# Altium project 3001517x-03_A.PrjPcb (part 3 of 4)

## Sheet 10 - CAN, I2C, XBee.SchDoc: CAN, I2C, XBee
size A3; PageSetup: Record=PageOptions¦CenterHorizontal=True¦CenterVertical=True¦PrintScale=0.70¦XCorrection=1.00¦YCorrection=1.00¦PrintKind=0¦BorderSize=5000000¦LeftOffset=0¦BottomOffset=0¦Orientation=2¦PaperLength=4200¦PaperWidth=2970¦Scale=100¦PaperSource=7¦PrintQuality=600¦MediaType=1¦DitherType=10¦PaperKind=A4¦PrintScaleMode=1; Author: Sébastien MEYER; SheetNumber: 10; SheetTotal: 14
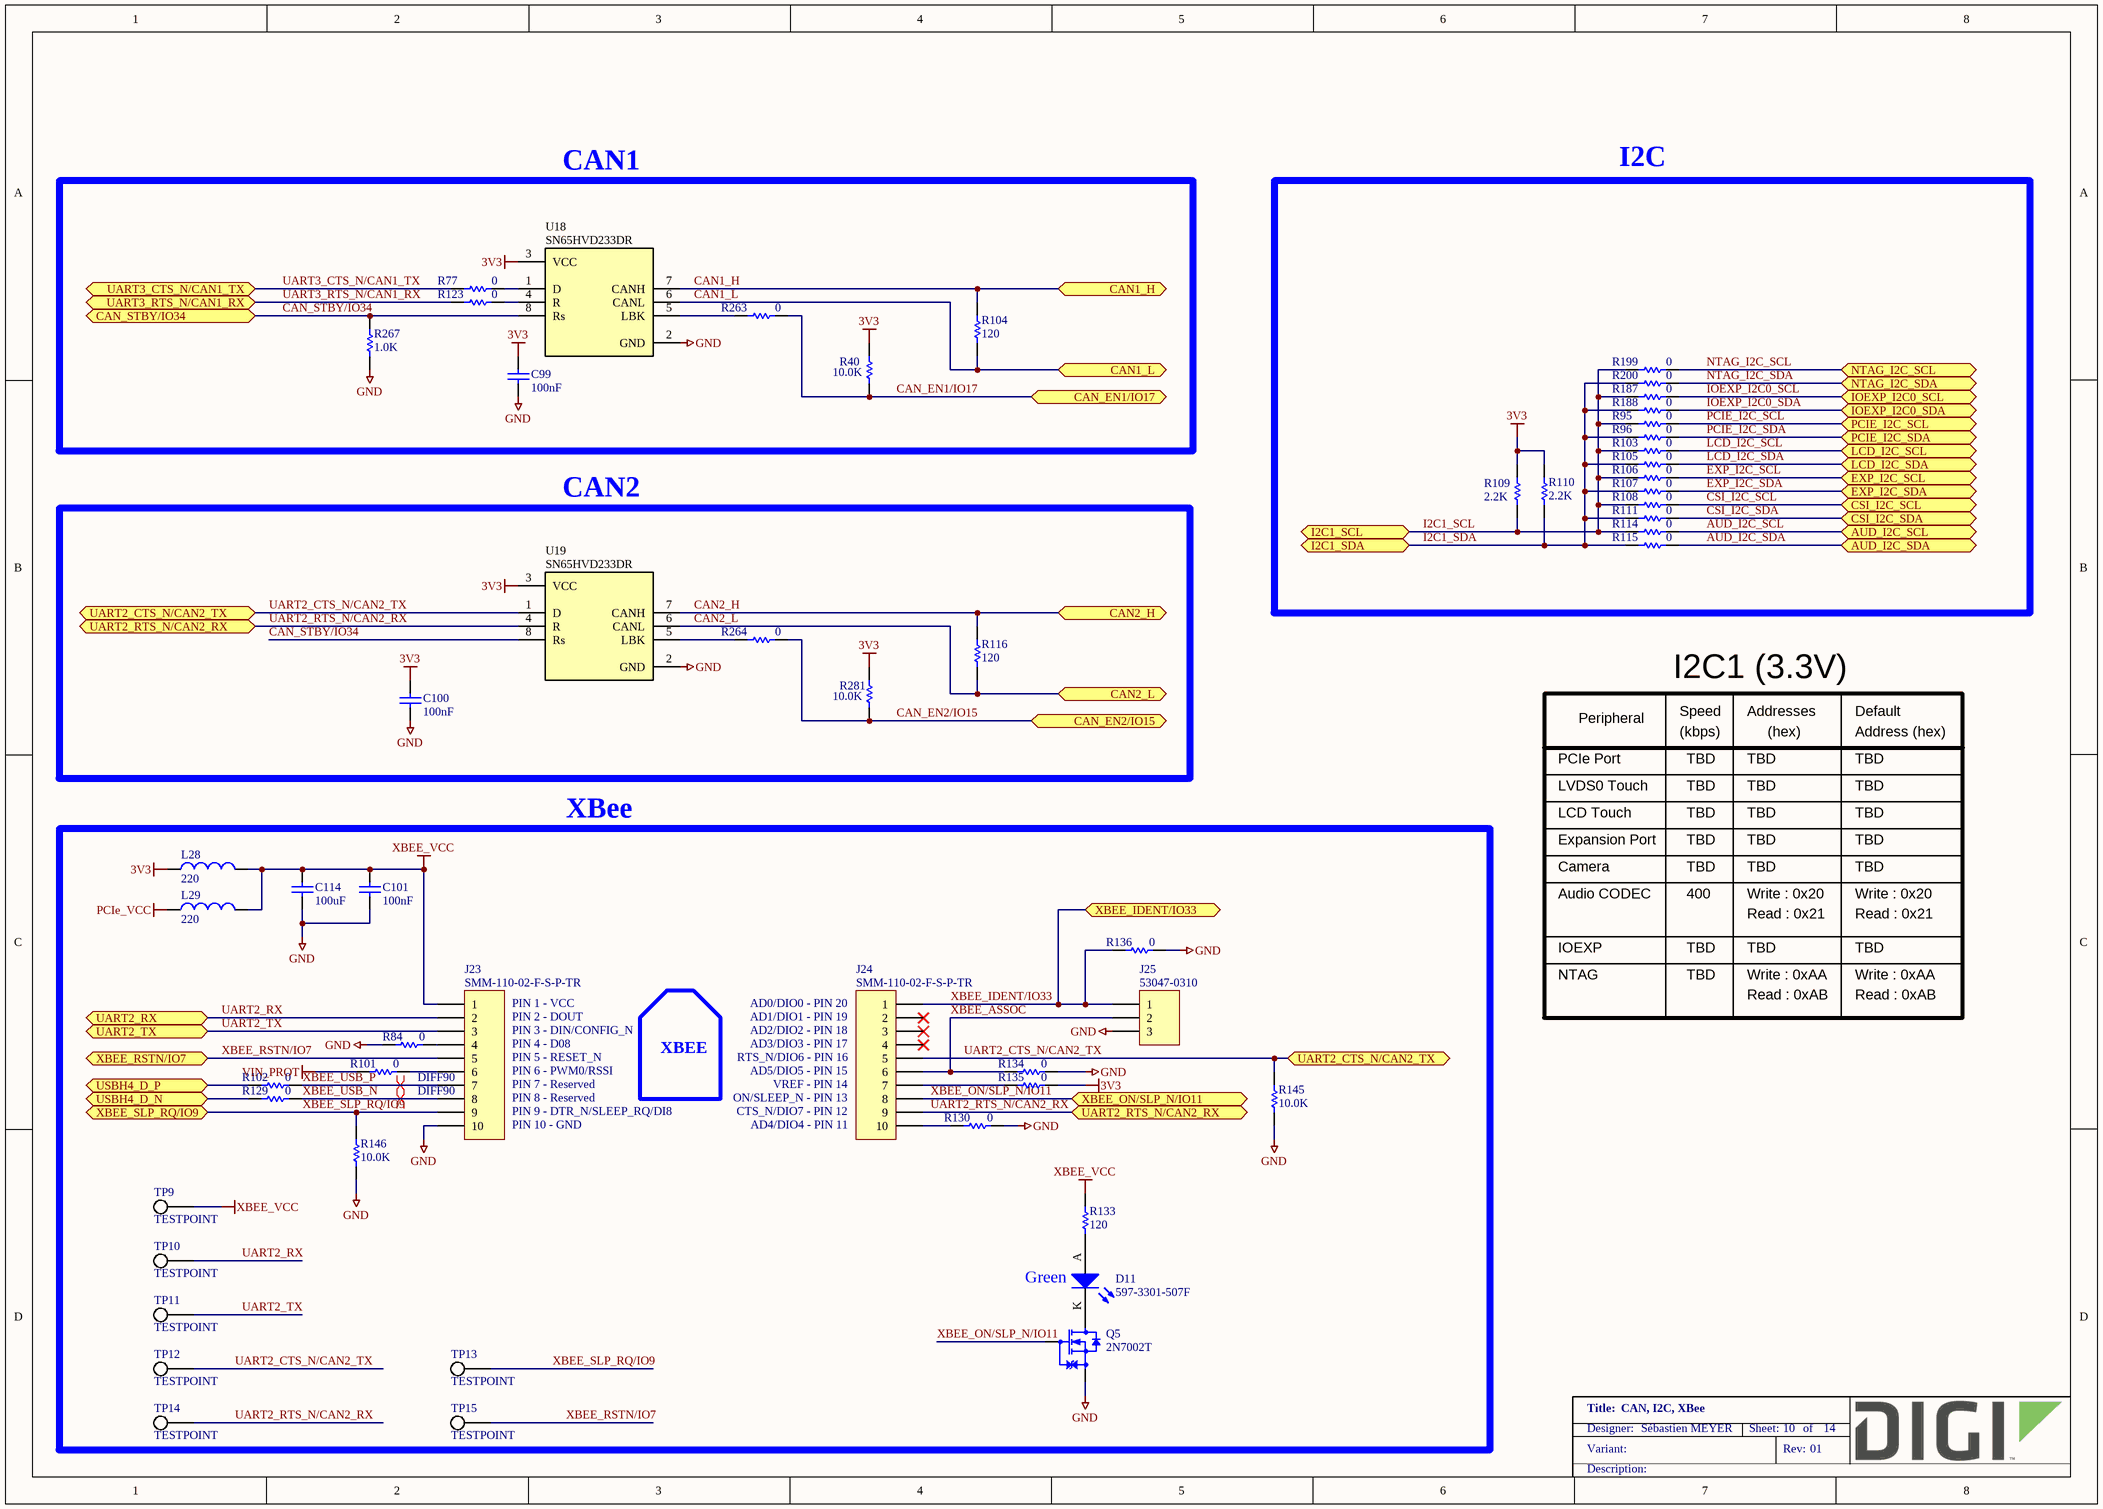
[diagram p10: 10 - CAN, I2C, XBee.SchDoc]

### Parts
C99  100nF  [CAPC1005X55N]
C100  100nF  [CAPC1005X55N]
C101  100nF  [CAPC1005X55N]
C114  100uF  [CAPC3216X190N]
D11  597-3301-507F  [LEDM3020X130N]
J23  SMM-110-02-F-S-P-TR  [Samtec_SMM-110-02-F-S]
J24  SMM-110-02-F-S-P-TR  [Samtec_SMM-110-02-F-S]
J25  Manufacturer_Part_Number: 53047-0310  [MOLEX_53047-0310]  (hidden comment: 1x3P)
L28  220  [INDC2013X110N]
L29  220  [INDC2013X110N]
Q5  2N7002T  [SOTFL50P160X80_GSD-3N]
R40  10.0K  [RESC1005X40N]
R77  0  [RESC1005X40N]
R84  0  [RESC1005X40N]
R95  0  [RESC1005X40N]
R96  0  [RESC1005X40N]
R101  0  [RESC1005X40N]
R102  0  [RESC1005X40N]
R103  0  [RESC1005X40N]
R104  120  [RESC1005X40N]
R105  0  [RESC1005X40N]
R106  0  [RESC1005X40N]
R107  0  [RESC1005X40N]
R108  0  [RESC1005X40N]
R109  2.2K  [RESC1005X40N]
R110  2.2K  [RESC1005X40N]
R111  0  [RESC1005X40N]
R114  0  [RESC1005X40N]
R115  0  [RESC1005X40N]
R116  120  [RESC1005X40N]
R123  0  [RESC1005X40N]
R129  0  [RESC1005X40N]
R130  0  [RESC1005X40N]
R133  120  [RESC1005X40N]
R134  0  [RESC1005X40N]
R135  0  [RESC1005X40N]
R136  0  [RESC1005X40N]
R145  10.0K  [RESC1005X40N]
R146  10.0K  [RESC1005X40N]
R187  0  [RESC1005X40N]
R188  0  [RESC1005X40N]
R199  0  [RESC1005X40N]
R200  0  [RESC1005X40N]
R263  0  [RESC1005X40N]
R264  0  [RESC1005X40N]
R267  1.0K  [RESC1005X40N]
R281  10.0K  [RESC1005X40N]
TP9  TESTPOINT  [TP0762]  (no BOM)
TP10  TESTPOINT  [TP0762]  (no BOM)
TP11  TESTPOINT  [TP0762]  (no BOM)
TP12  TESTPOINT  [TP0762]  (no BOM)
TP13  TESTPOINT  [TP0762]  (no BOM)
TP14  TESTPOINT  [TP0762]  (no BOM)
TP15  TESTPOINT  [TP0762]  (no BOM)
U18  SN65HVD233DR  [SOIC127P600X175-8N]
U19  SN65HVD233DR  [SOIC127P600X175-8N]

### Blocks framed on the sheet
CAN1: C99 R40 R77 R104 R123 R263 R267 U18
I2C: R95 R96 R103 R105-R111 R114 R115 R187 R188 R199 R200
CAN2: C100 R116 R264 R281 U19
XBee: C101 C114 D11 J23-J25 L28 L29 Q5 R84 R101 R102 R129 R130 R133-R136 R145 R146 TP9-TP15

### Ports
AUD_I2C_SCL (bidir), AUD_I2C_SDA (bidir), CAN1_H (bidir), CAN1_L (bidir), CAN2_H (bidir), CAN2_L (bidir), CAN_EN1/IO17 (bidir), CAN_EN2/IO15 (bidir), CAN_STBY/IO34 (bidir), CSI_I2C_SCL (bidir), CSI_I2C_SDA (bidir), EXP_I2C_SCL (bidir), EXP_I2C_SDA (bidir), I2C1_SCL (bidir), I2C1_SDA (bidir), IOEXP_I2C0_SCL (bidir), IOEXP_I2C0_SDA (bidir), LCD_I2C_SCL (bidir), LCD_I2C_SDA (bidir), NTAG_I2C_SCL (bidir), NTAG_I2C_SDA (bidir), PCIE_I2C_SCL (bidir), PCIE_I2C_SDA (bidir), UART2_CTS_N/CAN2_TX (bidir), UART2_RTS_N/CAN2_RX (bidir), UART2_RX (bidir), UART2_TX (bidir), UART3_CTS_N/CAN1_TX (bidir), UART3_RTS_N/CAN1_RX (bidir), USBH4_D_N (bidir), USBH4_D_P (bidir), XBEE_IDENT/IO33 (bidir), XBEE_ON/SLP_N/IO11 (bidir), XBEE_RSTN/IO7 (bidir), XBEE_SLP_RQ/IO9 (bidir)

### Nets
3V3: C99.2 C100.2 L28.1 R40.1 R109.2 R110.2 R135.2 R281.1 U18.3(VCC) U19.3(VCC)
GND: C99.1 C100.1 C101.1 C114.1 J23.10 J25.3 Q5.S R84.1 R130.2 R134.2 R136.2 R145.1 R146.1 R267.2 U18.2(GND) U19.2(GND)
PCIe_VCC: L29.1
VIN_PROT: R101.1
XBEE_VCC: C101.2 C114.2 J23.1 L28.2 L29.2 R133.1 TP9.1
AUD_I2C_SCL: R114.2 ; port AUD_I2C_SCL
AUD_I2C_SDA: R115.2 ; port AUD_I2C_SDA
CAN1_H: R104.2 U18.7(CANH) ; port CAN1_H
CAN1_L: R104.1 U18.6(CANL) ; port CAN1_L
CAN2_H: R116.2 U19.7(CANH) ; port CAN2_H
CAN2_L: R116.1 U19.6(CANL) ; port CAN2_L
CAN_EN1/IO17: R40.2 R263.2 ; port CAN_EN1/IO17
CAN_EN2/IO15: R264.2 R281.2 ; port CAN_EN2/IO15
CAN_STBY/IO34: R267.1 U18.8(Rs) U19.8(Rs) ; port CAN_STBY/IO34
CSI_I2C_SCL: R108.2 ; port CSI_I2C_SCL
CSI_I2C_SDA: R111.2 ; port CSI_I2C_SDA
EXP_I2C_SCL: R106.2 ; port EXP_I2C_SCL
EXP_I2C_SDA: R107.2 ; port EXP_I2C_SDA
I2C1_SCL: R95.1 R103.1 R106.1 R108.1 R109.1 R114.1 R187.1 R199.1 ; port I2C1_SCL
I2C1_SDA: R96.1 R105.1 R107.1 R110.1 R111.1 R115.1 R188.1 R200.1 ; port I2C1_SDA
IOEXP_I2C0_SCL: R187.2 ; port IOEXP_I2C0_SCL
IOEXP_I2C0_SDA: R188.2 ; port IOEXP_I2C0_SDA
LCD_I2C_SCL: R103.2 ; port LCD_I2C_SCL
LCD_I2C_SDA: R105.2 ; port LCD_I2C_SDA
NTAG_I2C_SCL: R199.2 ; port NTAG_I2C_SCL
NTAG_I2C_SDA: R200.2 ; port NTAG_I2C_SDA
PCIE_I2C_SCL: R95.2 ; port PCIE_I2C_SCL
PCIE_I2C_SDA: R96.2 ; port PCIE_I2C_SDA
UART2_CTS_N/CAN2_TX: J24.5 R145.2 TP12.1 U19.1(D) ; port UART2_CTS_N/CAN2_TX
UART2_RTS_N/CAN2_RX: J24.9 TP14.1 U19.4(R) ; port UART2_RTS_N/CAN2_RX
UART2_RX: J23.2 TP10.1 ; port UART2_RX
UART2_TX: J23.3 TP11.1 ; port UART2_TX
UART3_CTS_N/CAN1_TX: R77.1 ; port UART3_CTS_N/CAN1_TX
UART3_RTS_N/CAN1_RX: R123.1 ; port UART3_RTS_N/CAN1_RX
USBH4_D_N: R129.1 ; port USBH4_D_N
USBH4_D_P: R102.1 ; port USBH4_D_P
XBEE_ASSOC: J24.6 J25.2 R134.1
XBEE_IDENT/IO33: J24.1 J25.1 R136.1 ; port XBEE_IDENT/IO33
XBEE_ON/SLP_N/IO11: J24.8 Q5.G ; port XBEE_ON/SLP_N/IO11
XBEE_RSTN/IO7: J23.5 TP15.1 ; port XBEE_RSTN/IO7
XBEE_SLP_RQ/IO9: J23.9 R146.2 TP13.1 ; port XBEE_SLP_RQ/IO9
XBEE_USB_N: J23.8 R129.2
XBEE_USB_P: J23.7 R102.2
NetD11_A: D11.A R133.2
NetD11_K: D11.K Q5.D
NetJ23_4: J23.4 R84.2
NetJ23_6: J23.6 R101.2
NetJ24_7: J24.7 R135.1
NetJ24_10: J24.10 R130.1
NetR77_2: R77.2 U18.1(D)
NetR123_2: R123.2 U18.4(R)
NetR263_1: R263.1 U18.5(LBK)
NetR264_1: R264.1 U19.5(LBK)

Not connected (* = marked no-connect by the designer): J24 2* 3* 4*

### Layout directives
differential pair; net class DIFF90: XBEE_USB_N, XBEE_USB_P

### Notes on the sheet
- Peripheral
- I2C1 (3.3V)
- Speed
- Addresses
- Default
- PCIe Port
- (kbps)
- TBD
- (hex)
- Address (hex)
- LVDS0 Touch
- LCD Touch
- Expansion Port
- Camera
- Audio CODEC
- 400
- Write : 0x20
- Read : 0x21
- IOEXP
- NTAG
- Write : 0xAA
- (near J23) PIN 1 - VCC
- (near J23) PIN 2 - DOUT
- (near J23) PIN 3 - DIN/CONFIG_N
- (near J23) PIN 4 - D08
- XBEE
- (near J24) AD0/DIO0 - PIN 20
- (near J24) AD1/DIO1 - PIN 19
- (near J24) AD2/DIO2 - PIN 18
- (near J24) AD3/DIO3 - PIN 17
- Read : 0xAB
- (near J23) PIN 5 - RESET_N
- (near J23) PIN 6 - PWM0/RSSI
- (near J23) PIN 7 - Reserved
- (near J23) PIN 8 - Reserved
- (near J23) PIN 9 - DTR_N/SLEEP_RQ/DI8
- (near J23) PIN 10 - GND
- (near J24) RTS_N/DIO6 - PIN 16
- (near J24) AD5/DIO5 - PIN 15
- (near J24) VREF - PIN 14
- (near J24) ON/SLEEP_N - PIN 13
- (near J24) CTS_N/DIO7 - PIN 12
- (near J24) AD4/DIO4 - PIN 11
- (near D11) Green

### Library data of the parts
C99-C101 = 1000006: CAP 100nF 16V 10% X7R 0402; Part_Type: Capacitor; Manufacturer: Murata; Manufacturer_Part_Number: GRM155R71C104KA88D; Component_Life_Cycle_State: CAD Reviewed; Area: 0.95; Project: KITT; Tolerance: 10; Digi_PN: 14050552
C114 = 1000566: CAP CER 100UF 10V 20% X5R 1206; Part_Type: Capacitor; Manufacturer: TDK Corporation; Manufacturer_Part_Number: C3216X5R1A107M; Digi_PN: 14050666; Component_Life_Cycle_State: Reviewed; Area: 7.47; Project: GSM Cell PCB
D11 = 1001189: LED GREEN 573NM 1208 SMD; Manufacturer: Dialight; Digi_PN: 17050183; Component_Life_Cycle_State: Reviewed; Area: 6; Project: CCWMX6_SBC board; Note: 17050846 = Digi PN for GE WDNU II
J23 J24 = 1001495: CONN RCPT 2MM 10POS SMD; Part_Type: Connector; Manufacturer: Samtec; Digi_PN: 19050036; Component_Life_Cycle_State: Reviewed; Area: 105; Project: CCWMX6_SBC board
J25 = 1001183: CONN HEADER 3POS 1.25MM VERT TIN; Part_Type: Connector; Manufacturer: Molex; Digi_PN: 18050349; Component_Life_Cycle_State: Reviewed; Area: 17.6; Project: CCWMX6_SBC board
L28 L29 = 1001174: FERRITE BEAD 220 OHM 2.0A 0805; Manufacturer: Wurth Electronics Inc; Manufacturer_Part_Number: 742792022; Digi_PN: 21000146; Component_Life_Cycle_State: Reviewed; Area: 4.24; Project: CCWMX6_SBC board
Q5 = 1000715: MOSFET N-CH 60V 115MA SOT-523F; Part_Type: Transistor; Manufacturer: Fairchild Semiconductor; Digi_PN: 17050797; Component_Life_Cycle_State: CAD Reviewed; Area: 3.06; Project: SmartMeter2; Note: 17050841 = Digi No. for GE WDNU
R40 R145 R146 R281 = 1000537: RES 10.0K OHM 1/10W 1% 0402 SMD; Part_Type: Resistor; Manufacturer: Panasonic - ECG; Manufacturer_Part_Number: ERJ-2RKF1002X; Component_Life_Cycle_State: CAD Reviewed; Area: 0.95; Project: KITT; Power_WV_SRF: 100; Digi_PN: 13051084
R77 R84 R95 R96 R101-R103 R105-R108 R111 R114 R115 R123 R129 R130 R134-R136 R187 R188 R199 R200 R263 R264 = 1000076: RES 0.0 OHM 1/10W 0402 SMD; Part_Type: Resistor; Manufacturer: Panasonic - ECG; Manufacturer_Part_Number: ERJ-2GE0R00X; Component_Life_Cycle_State: Proven; Area: 0.95; Project: Adjustable Foundation; Power_WV_SRF: 10; Digi_PN: 13050387
R104 R116 R133 = 1001158: RES 120 OHM 1/16W 1% 0402 SMD; Part_Type: Resistor; Manufacturer: Yageo; Manufacturer_Part_Number: RC0402FR-07120RL; Digi_PN: 13050832; Component_Life_Cycle_State: Reviewed; Area: 0.95; Project: CCWMX6_SBC board; Note: 13051102 = Digi No. for GE WDNU
R109 R110 = 1001156: RES 2.20K OHM 1/16W 1% 0402 SMD; Part_Type: Resistor; Manufacturer: Yageo; Manufacturer_Part_Number: RC0402FR-072K2L; Digi_PN: 13050699; Component_Life_Cycle_State: Reviewed; Area: 0.95; Project: CCWMX6_SBC board; Note: 13051099 = Digi No. for GE WDNU
R267 = 1000079: RES 1.00K OHM 1/10W 1% 0402 SMD; Part_Type: Resistor; Manufacturer: Panasonic - ECG; Manufacturer_Part_Number: ERJ-2RKF1001X; Digi_PN: 13051085; Component_Life_Cycle_State: Proven; Area: 0.95; Project: Adjustable Foundation; Power_WV_SRF: 10
TP9-TP15 = CAD0011: TEST POINT 30mil PAD SMT; Component_Life_Cycle_State: Reviewed; Area: 0.58; Project: CLC
U18 U19 = 1001129: IC CAN TRANSCEIVER 3.3V 8-SOIC; Manufacturer: Texas Instruments; Digi_PN: TA02540; Component_Life_Cycle_State: Reviewed; Area: 20; Project: CCWMX6_SBC board

## Sheet 11 - Expansion Connectors, User LEDs, NTAG.SchDoc: Expansion Connectors, User LEDs, NTAG
size A3; PageSetup: Record=PageOptions¦CenterHorizontal=True¦CenterVertical=True¦PrintScale=0.70¦XCorrection=1.00¦YCorrection=1.00¦PrintKind=0¦BorderSize=5000000¦LeftOffset=0¦BottomOffset=0¦Orientation=2¦PaperLength=4200¦PaperWidth=2970¦Scale=100¦PaperSource=7¦PrintQuality=600¦MediaType=1¦DitherType=10¦PaperKind=A4¦PrintScaleMode=1; Author: Sébastien MEYER; SheetNumber: 11; SheetTotal: 14
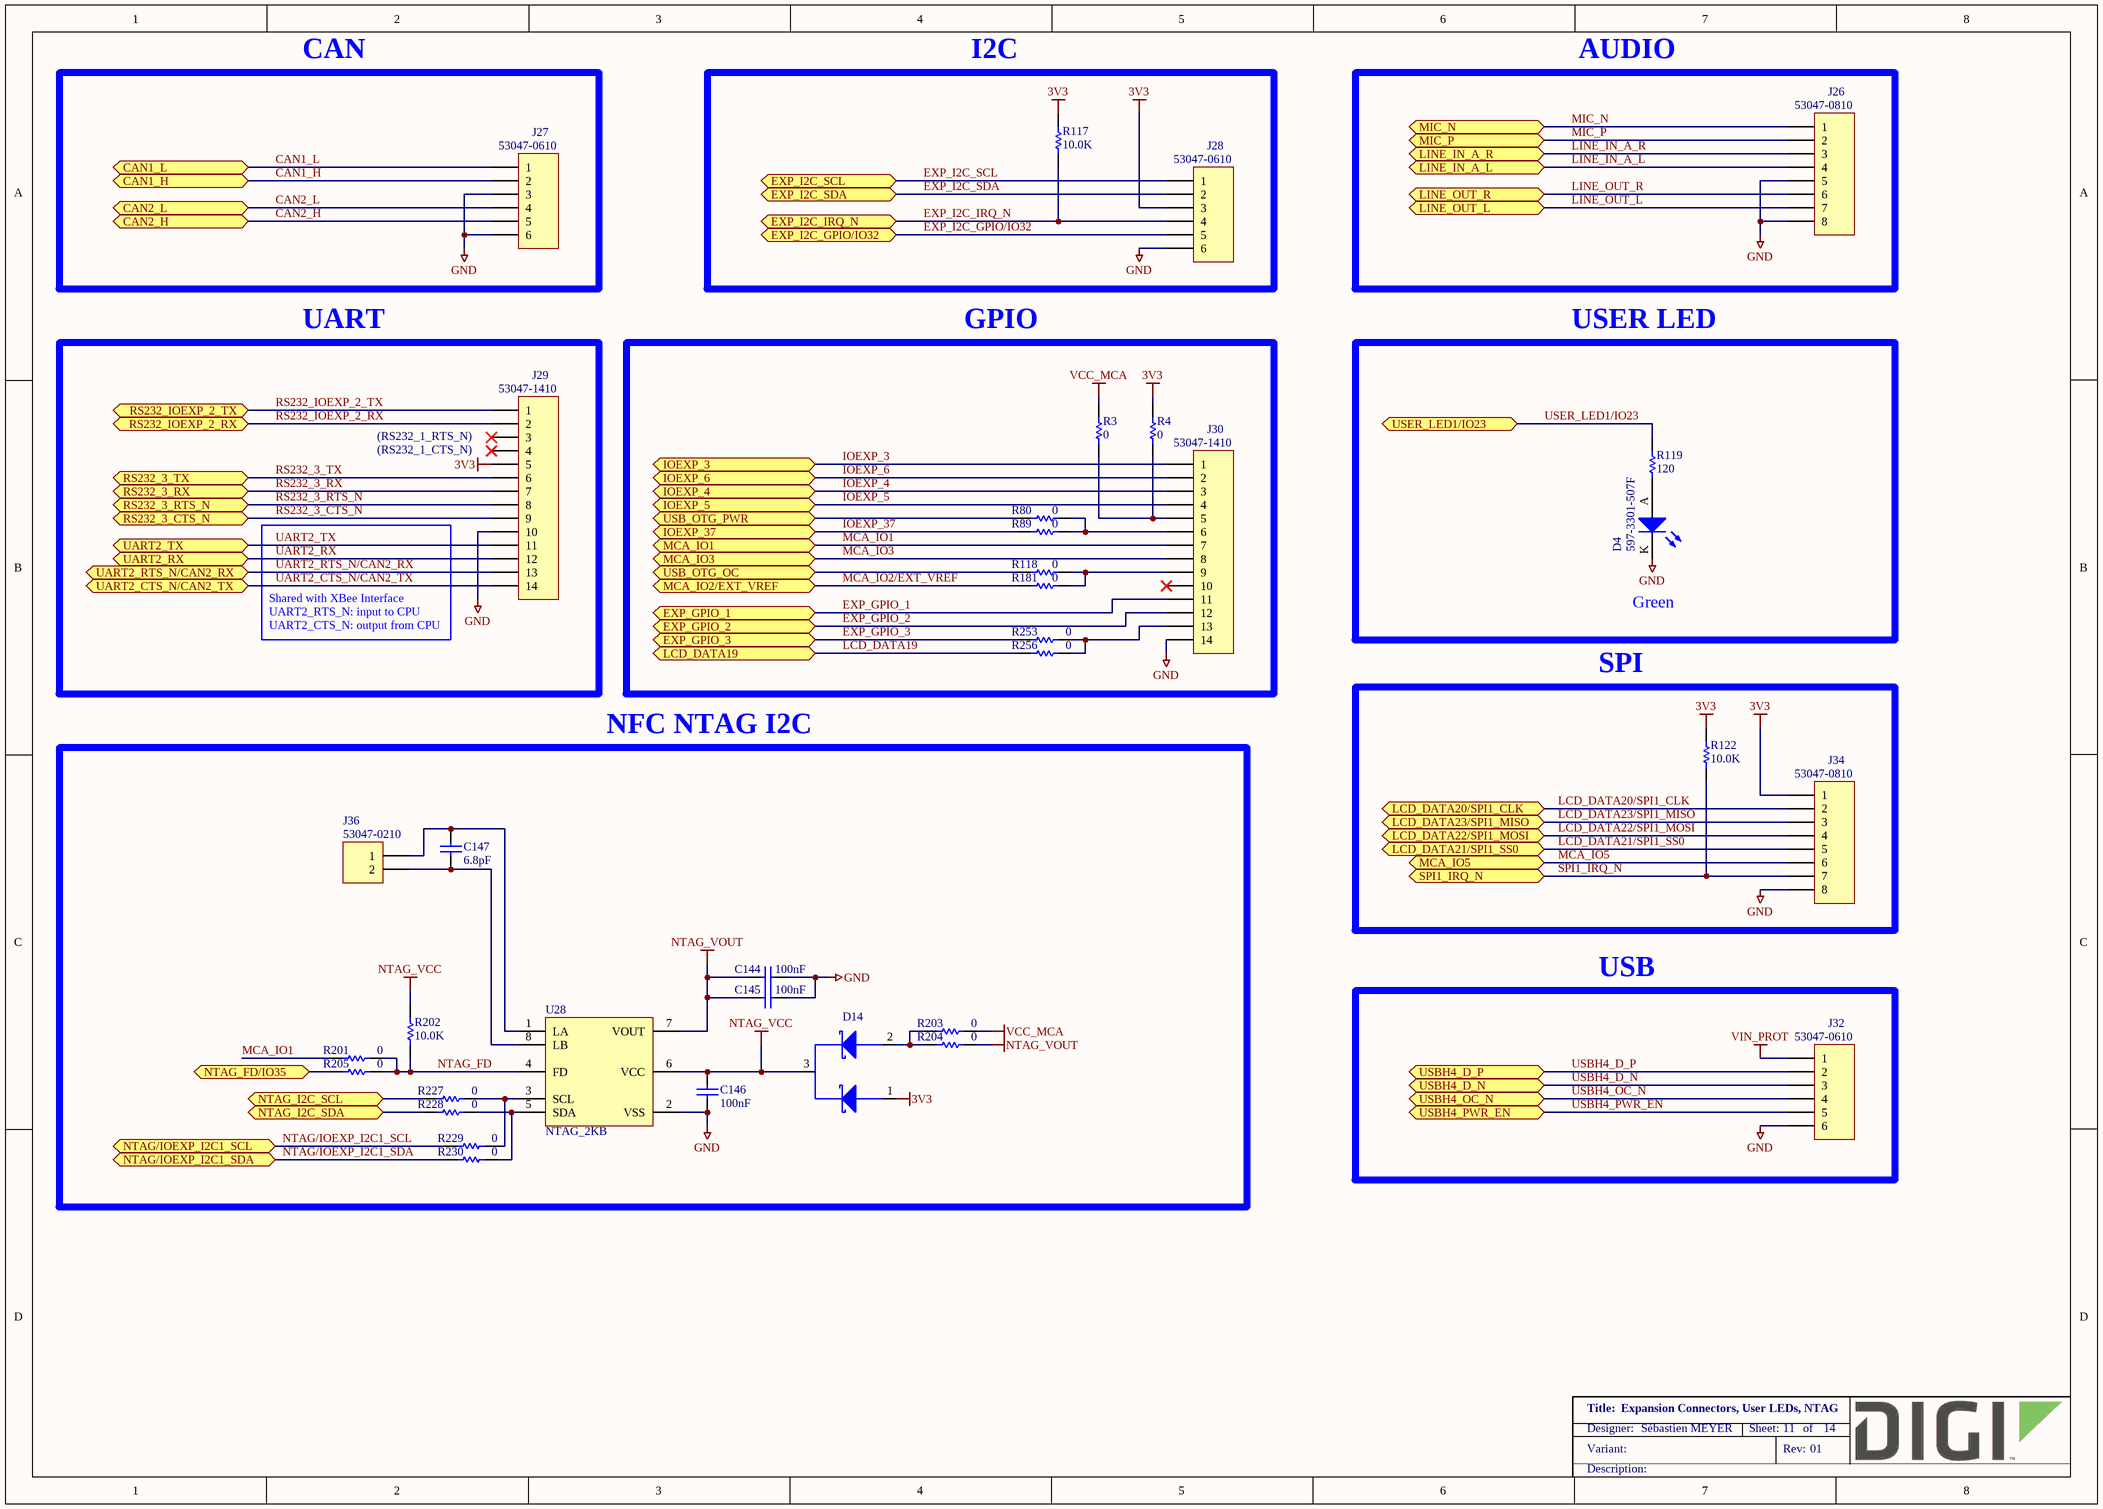
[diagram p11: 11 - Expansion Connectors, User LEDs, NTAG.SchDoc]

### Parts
C144  100nF  [CAPC1005X55N]
C145  100nF  [CAPC1005X55N]
C146  100nF  [CAPC1005X55N]
C147  6.8pF  [CAPC1005X55N]
D4  597-3301-507F  [LEDM3020X130N]
D14  BAT54CWT1G  [SOT65P210X100-3AN]  (value not drawn)
J26  Manufacturer_Part_Number: 53047-0810  [MOLEX_53047-0810]  (hidden comment: 1x8P)
J27  Manufacturer_Part_Number: 53047-0610  [MOLEX_53047-0610]  (hidden comment: 1x6P)
J28  Manufacturer_Part_Number: 53047-0610  [MOLEX_53047-0610]  (hidden comment: 1x6P)
J29  Manufacturer_Part_Number: 53047-1410  [MOLEX_53047-1410]  (hidden comment: 1x14P)
J30  Manufacturer_Part_Number: 53047-1410  [MOLEX_53047-1410]  (hidden comment: 1x14P)
J32  Manufacturer_Part_Number: 53047-0610  [MOLEX_53047-0610]  (hidden comment: 1x6P)
J34  Manufacturer_Part_Number: 53047-0810  [MOLEX_53047-0810]  (hidden comment: 1x8P)
J36  Manufacturer_Part_Number: 53047-0210  [MOLEX_53047-0210]  (hidden comment: 1x2P)
R3  0  [RESC1005X40N]
R4  0  [RESC1005X40N]
R80  0  [RESC1005X40N]
R89  0  [RESC1005X40N]
R117  10.0K  [RESC1005X40N]
R118  0  [RESC1005X40N]
R119  120  [RESC1005X40N]
R122  10.0K  [RESC1005X40N]
R181  0  [RESC1005X40N]
R201  0  [RESC1005X40N]
R202  10.0K  [RESC1005X40N]
R203  0  [RESC1005X40N]
R204  0  [RESC1005X40N]
R205  0  [RESC1005X40N]
R227  0  [RESC1005X40N]
R228  0  [RESC1005X40N]
R229  0  [RESC1005X40N]
R230  0  [RESC1005X40N]
R253  0  [RESC1005X40N]
R256  0  [RESC1005X40N]
U28  NTAG_2KB  [NXP_XQFN8]

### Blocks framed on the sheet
CAN: J27
I2C: J28 R117
AUDIO: J26
UART: J29
GPIO: J30 R3 R4 R80 R89 R118 R181 R253 R256
USER LED: D4 R119
SPI: J34 R122
NFC NTAG I2C: C144-C147 D14 J36 R201-R205 R227-R230 U28
USB: J32

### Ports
CAN1_H (bidir), CAN1_L (bidir), CAN2_H (bidir), CAN2_L (bidir), EXP_GPIO_1 (bidir), EXP_GPIO_2 (bidir), EXP_GPIO_3 (bidir), EXP_I2C_GPIO/IO32 (bidir), EXP_I2C_IRQ_N (bidir), EXP_I2C_SCL (bidir), EXP_I2C_SDA (bidir), IOEXP_3 (bidir), IOEXP_4 (bidir), IOEXP_5 (bidir), IOEXP_6 (bidir), IOEXP_37 (bidir), LCD_DATA19 (bidir), LCD_DATA20/SPI1_CLK (bidir), LCD_DATA21/SPI1_SS0 (bidir), LCD_DATA22/SPI1_MOSI (bidir), LCD_DATA23/SPI1_MISO (bidir), LINE_IN_A_L (bidir), LINE_IN_A_R (bidir), LINE_OUT_L (bidir), LINE_OUT_R (bidir), MCA_IO1 (bidir), MCA_IO2/EXT_VREF (bidir), MCA_IO3 (bidir), MCA_IO5 (bidir), MIC_N (bidir), MIC_P (bidir), NTAG/IOEXP_I2C1_SCL (bidir), NTAG/IOEXP_I2C1_SDA (bidir), NTAG_FD/IO35 (bidir), NTAG_I2C_SCL (bidir), NTAG_I2C_SDA (bidir), RS232_3_CTS_N (bidir), RS232_3_RTS_N (bidir), RS232_3_RX (bidir), RS232_3_TX (bidir), RS232_IOEXP_2_RX (bidir), RS232_IOEXP_2_TX (bidir), SPI1_IRQ_N (bidir), UART2_CTS_N/CAN2_TX (bidir), UART2_RTS_N/CAN2_RX (bidir), UART2_RX (bidir), UART2_TX (bidir), USB_OTG_OC (bidir), USB_OTG_PWR (bidir), USBH4_D_N (bidir), USBH4_D_P (bidir), USBH4_OC_N (bidir), USBH4_PWR_EN (bidir), USER_LED1/IO23 (bidir)

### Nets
3V3: D14.1 J28.3 J29.5 J34.1 R4.2 R117.1 R122.1
GND: C144.1 C145.1 C146.1 D4.K J26.5 J26.8 J27.3 J27.6 J28.6 J29.10 J30.14 J32.6 J34.8 U28.2(VSS)
NTAG_VCC: C146.2 D14.3 R202.1 U28.6(VCC)
NTAG_VOUT: C144.2 C145.2 R204.2 U28.7(VOUT)
VCC_MCA: R3.2 R203.2
VIN_PROT: J32.1
CAN1_H: J27.2 ; port CAN1_H
CAN1_L: J27.1 ; port CAN1_L
CAN2_H: J27.5 ; port CAN2_H
CAN2_L: J27.4 ; port CAN2_L
EXP_GPIO_1: J30.11 ; port EXP_GPIO_1
EXP_GPIO_2: J30.12 ; port EXP_GPIO_2
EXP_GPIO_3: R253.2 ; port EXP_GPIO_3
EXP_I2C_GPIO/IO32: J28.5 ; port EXP_I2C_GPIO/IO32
EXP_I2C_IRQ_N: J28.4 R117.2 ; port EXP_I2C_IRQ_N
EXP_I2C_SCL: J28.1 ; port EXP_I2C_SCL
EXP_I2C_SDA: J28.2 ; port EXP_I2C_SDA
IOEXP_3: J30.1 ; port IOEXP_3
IOEXP_4: J30.3 ; port IOEXP_4
IOEXP_5: J30.4 ; port IOEXP_5
IOEXP_6: J30.2 ; port IOEXP_6
IOEXP_37: R89.1 ; port IOEXP_37
LCD_DATA19: R256.2 ; port LCD_DATA19
LCD_DATA20/SPI1_CLK: J34.2 ; port LCD_DATA20/SPI1_CLK
LCD_DATA21/SPI1_SS0: J34.5 ; port LCD_DATA21/SPI1_SS0
LCD_DATA22/SPI1_MOSI: J34.4 ; port LCD_DATA22/SPI1_MOSI
LCD_DATA23/SPI1_MISO: J34.3 ; port LCD_DATA23/SPI1_MISO
LINE_IN_A_L: J26.4 ; port LINE_IN_A_L
LINE_IN_A_R: J26.3 ; port LINE_IN_A_R
LINE_OUT_L: J26.7 ; port LINE_OUT_L
LINE_OUT_R: J26.6 ; port LINE_OUT_R
MCA_IO1: J30.7 R201.1 ; port MCA_IO1
MCA_IO2/EXT_VREF: R181.1 ; port MCA_IO2/EXT_VREF
MCA_IO3: J30.8 ; port MCA_IO3
MCA_IO5: J34.6 ; port MCA_IO5
MIC_N: J26.1 ; port MIC_N
MIC_P: J26.2 ; port MIC_P
NTAG/IOEXP_I2C1_SCL: R229.1 ; port NTAG/IOEXP_I2C1_SCL
NTAG/IOEXP_I2C1_SDA: R230.1 ; port NTAG/IOEXP_I2C1_SDA
NTAG_FD: R201.2 R202.2 R205.2 U28.4(FD)
NTAG_FD/IO35: R205.1 ; port NTAG_FD/IO35
NTAG_I2C_SCL: R227.1 ; port NTAG_I2C_SCL
NTAG_I2C_SDA: R228.1 ; port NTAG_I2C_SDA
RS232_3_CTS_N: J29.9 ; port RS232_3_CTS_N
RS232_3_RTS_N: J29.8 ; port RS232_3_RTS_N
RS232_3_RX: J29.7 ; port RS232_3_RX
RS232_3_TX: J29.6 ; port RS232_3_TX
RS232_IOEXP_2_RX: J29.2 ; port RS232_IOEXP_2_RX
RS232_IOEXP_2_TX: J29.1 ; port RS232_IOEXP_2_TX
SPI1_IRQ_N: J34.7 R122.2 ; port SPI1_IRQ_N
UART2_CTS_N/CAN2_TX: J29.14 ; port UART2_CTS_N/CAN2_TX
UART2_RTS_N/CAN2_RX: J29.13 ; port UART2_RTS_N/CAN2_RX
UART2_RX: J29.12 ; port UART2_RX
UART2_TX: J29.11 ; port UART2_TX
USB_OTG_OC: R118.1 ; port USB_OTG_OC
USB_OTG_PWR: R80.1 ; port USB_OTG_PWR
USBH4_D_N: J32.3 ; port USBH4_D_N
USBH4_D_P: J32.2 ; port USBH4_D_P
USBH4_OC_N: J32.4 ; port USBH4_OC_N
USBH4_PWR_EN: J32.5 ; port USBH4_PWR_EN
USER_LED1/IO23: R119.2 ; port USER_LED1/IO23
NetC147_1: C147.1 J36.2 U28.8(LB)
NetC147_2: C147.2 J36.1 U28.1(LA)
NetD4_A: D4.A R119.1
NetD14_2: D14.2 R203.1 R204.1
NetJ30_5: J30.5 R3.1 R4.1
NetJ30_6: J30.6 R80.2 R89.2
NetJ30_9: J30.9 R118.2 R181.2
NetJ30_13: J30.13 R253.1 R256.1
NetR227_2: R227.2 R229.2 U28.3(SCL)
NetR228_2: R228.2 R230.2 U28.5(SDA)

Not connected (* = marked no-connect by the designer): J29 3* 4*; J30 10*

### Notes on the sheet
- (near J29) (RS232_1_RTS_N)
- (near J29) (RS232_1_CTS_N)
- Shared with XBee Interface
- UART2_RTS_N: input to CPU
- UART2_CTS_N: output from CPU
- Green

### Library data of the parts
C144-C146 = 1000006: as C99-C101 on sheet 10 - CAN, I2C, XBee
C147 = 1001679: CAP CER 6.8PF 50V NP0 0402; Part_Type: Capacitor; Manufacturer: Murata; Manufacturer_Part_Number: GRM1555C1H6R8CA01D; Note: 14050752 = Digi No. for GE WDNU; Digi_PN: 14050360; Component_Life_Cycle_State: Reviewed; Area: 2,5; Project: WDNU-II; Tolerance: 0.25pF; Temp_Coef: C0G, NP0
D4 = 1001189: as D11 on sheet 10 - CAN, I2C, XBee
D14 = 1000794: DIODE SCHOTTKY 30V 200MA SOT323; Part Number: SDS1920004; Manufacturer: Fairchild Semiconductor; Manufacturer Alt 1: none; Manufacturer Part Num: 0082610201; Part_Type: Diodes; Digi_PN: 17050561; Component_Life_Cycle_State: CAD Reviewed; Area: 7,68; Project: SmartMeter2
J26 J34 = 1001139: CONN HEADER 8POS 1.25MM VERT TIN; Part_Type: Connector; Manufacturer: Molex; Digi_PN: 18050346; Component_Life_Cycle_State: Reviewed; Area: 37.6; Project: CCWMX6_SBC board
J27 J28 J32 = 1001138: CONN HEADER 6POS 1.25MM VERT TIN; Part_Type: Connector; Manufacturer: Molex; Digi_PN: 18050345; Component_Life_Cycle_State: Reviewed; Area: 29.6; Project: CCWMX6_SBC board
J29 J30 = 1001140: CONN HEADER 14POS 1.25MM STR TIN; Part_Type: Connector; Manufacturer: Molex; Digi_PN: 18050347; Component_Life_Cycle_State: Reviewed; Area: 61.6; Project: CCWMX6_SBC board
J36 = 1001136: CONN HEADER 2POS 1.25MM VERT TIN; Part_Type: Connector; Manufacturer: Molex; Component_Life_Cycle_State: Reviewed; Area: 13.6; Project: CCWMX6_SBC board; Digi_PN: 18050343
R3 R4 R80 R89 R118 R181 R201 R203-R205 R227-R230 R253 R256 = 1000076: as R77 on sheet 10 - CAN, I2C, XBee
R117 R122 R202 = 1000537: as R40 on sheet 10 - CAN, I2C, XBee
R119 = 1001158: as R104 on sheet 10 - CAN, I2C, XBee
U28 = 1002006: IC SMART TAG , 2KB; Manufacturer: NXP Semiconductors; Manufacturer_Part_Number: NT3H1201W0FHK; Digi_PN: 16051984; Component_Life_Cycle_State: Created; Area: 8,07; Project: iMX6UL+PMIC

## Sheet 12 - Bootstrap.SchDoc: Bootstrap
size A3; PageSetup: Record=PageOptions¦CenterHorizontal=True¦CenterVertical=True¦PrintScale=1.01¦XCorrection=1.00¦YCorrection=1.00¦PrintKind=0¦BorderSize=5000000¦LeftOffset=0¦BottomOffset=0¦Orientation=2¦PaperLength=4200¦PaperWidth=2970¦Scale=100¦PaperSource=15¦PrintQuality=600¦MediaType=1¦DitherType=10¦PrintScaleMode=1¦PaperKind=A3¦PaperIndex=8; Author: Sébastien MEYER; SheetNumber: 12; SheetTotal: 14
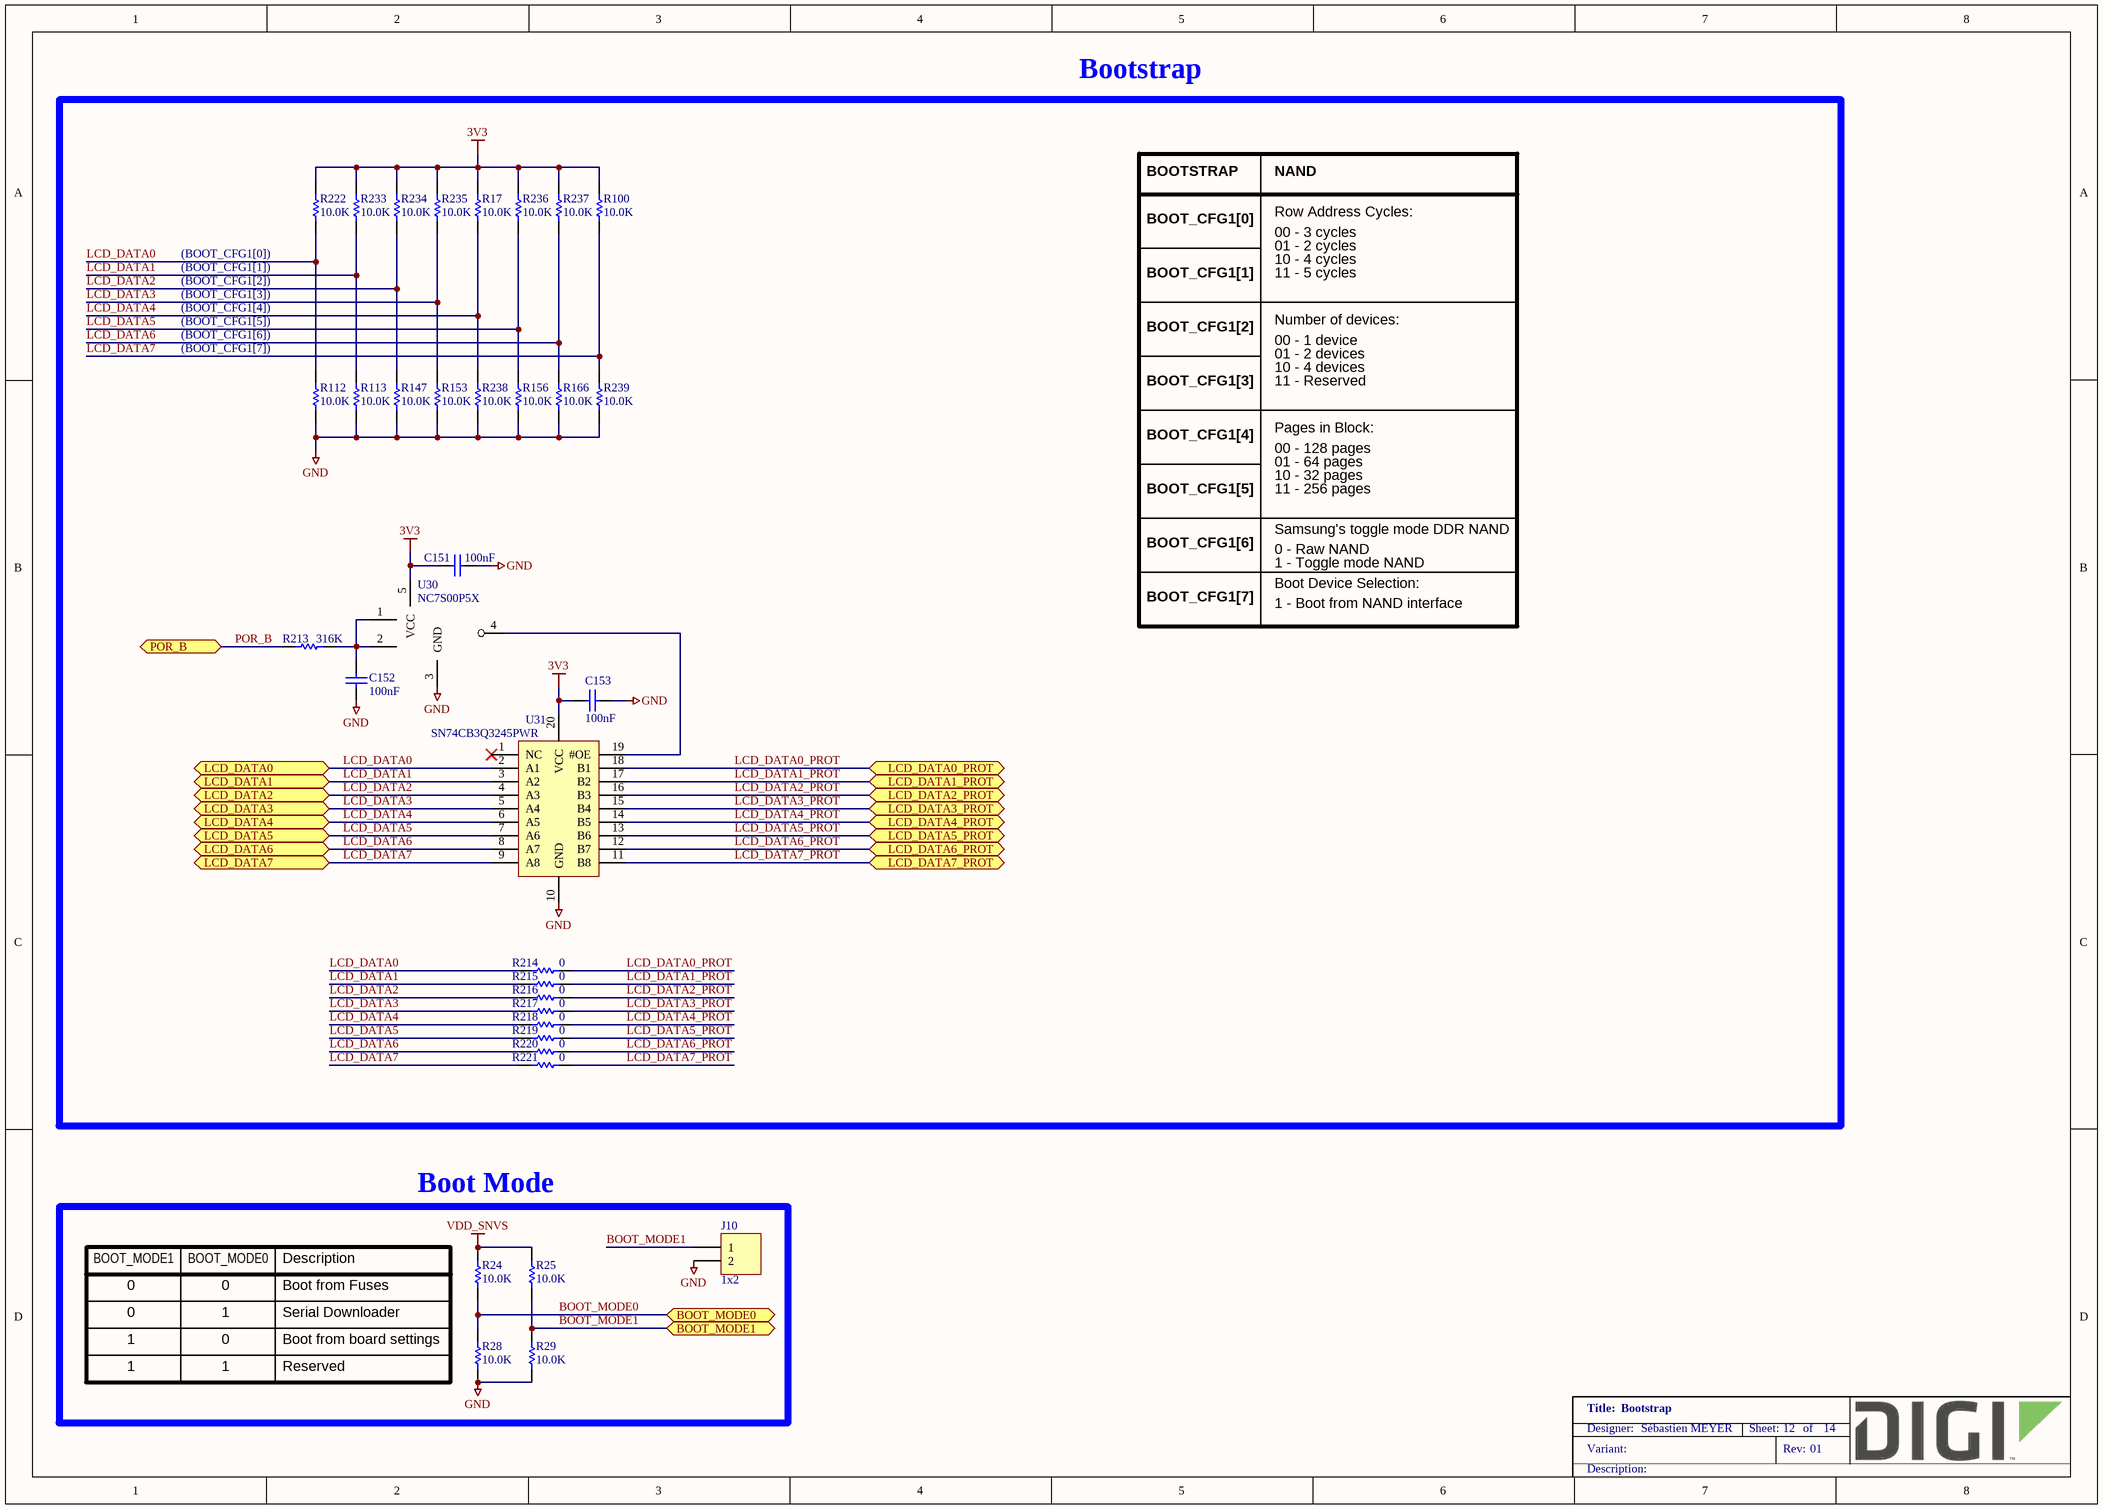
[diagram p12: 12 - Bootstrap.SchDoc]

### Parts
C151  100nF  [CAPC1005X55N]
C152  100nF  [CAPC1005X55N]
C153  100nF  [CAPC1005X55N]
J10  1x2  [FCI_68002-102HLF]
R17  10.0K  [RESC1005X40N]
R24  10.0K  [RESC1005X40N]
R25  10.0K  [RESC1005X40N]
R28  10.0K  [RESC1005X40N]
R29  10.0K  [RESC1005X40N]
R100  10.0K  [RESC1005X40N]
R112  10.0K  [RESC1005X40N]
R113  10.0K  [RESC1005X40N]
R147  10.0K  [RESC1005X40N]
R153  10.0K  [RESC1005X40N]
R156  10.0K  [RESC1005X40N]
R166  10.0K  [RESC1005X40N]
R213  316K  [RESC1609X55N]
R214  0  [RESC1005X40N]
R215  0  [RESC1005X40N]
R216  0  [RESC1005X40N]
R217  0  [RESC1005X40N]
R218  0  [RESC1005X40N]
R219  0  [RESC1005X40N]
R220  0  [RESC1005X40N]
R221  0  [RESC1005X40N]
R222  10.0K  [RESC1005X40N]
R233  10.0K  [RESC1005X40N]
R234  10.0K  [RESC1005X40N]
R235  10.0K  [RESC1005X40N]
R236  10.0K  [RESC1005X40N]
R237  10.0K  [RESC1005X40N]
R238  10.0K  [RESC1005X40N]
R239  10.0K  [RESC1005X40N]
U30  NC7S00P5X  [SOT65P210X110-5N]
U31  SN74CB3Q3245PWR  [SOP65P640X120-20N]

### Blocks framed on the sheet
Bootstrap: C151-C153 R17 R100 R112 R113 R147 R153 R156 R166 R213-R222 R233-R239 U30 U31
Boot Mode: J10 R24 R25 R28 R29

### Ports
BOOT_MODE0 (bidir), BOOT_MODE1 (bidir), LCD_DATA0 (bidir), LCD_DATA0_PROT (bidir), LCD_DATA1 (bidir), LCD_DATA1_PROT (bidir), LCD_DATA2 (bidir), LCD_DATA2_PROT (bidir), LCD_DATA3 (bidir), LCD_DATA3_PROT (bidir), LCD_DATA4 (bidir), LCD_DATA4_PROT (bidir), LCD_DATA5 (bidir), LCD_DATA5_PROT (bidir), LCD_DATA6 (bidir), LCD_DATA6_PROT (bidir), LCD_DATA7 (bidir), LCD_DATA7_PROT (bidir), POR_B (bidir)

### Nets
3V3: C151.1 C153.2 R17.2 R100.2 R222.2 R233.2 R234.2 R235.2 R236.2 R237.2 U30.5(VCC) U31.20(VCC)
GND: C151.2 C152.1 C153.1 J10.2 R28.2 R29.2 R112.1 R113.1 R147.1 R153.1 R156.1 R166.1 R238.1 R239.1 U30.3(GND) U31.10(GND)
VDD_SNVS: R24.1 R25.1
BOOT_MODE0: R24.2 R28.1 ; port BOOT_MODE0
BOOT_MODE1: J10.1 R25.2 R29.1 ; port BOOT_MODE1
LCD_DATA0: R112.2 R214.1 R222.1 U31.2(A1) ; port LCD_DATA0
LCD_DATA0_PROT: R214.2 U31.18(B1) ; port LCD_DATA0_PROT
LCD_DATA1: R113.2 R215.1 R233.1 U31.3(A2) ; port LCD_DATA1
LCD_DATA1_PROT: R215.2 U31.17(B2) ; port LCD_DATA1_PROT
LCD_DATA2: R147.2 R216.1 R234.1 U31.4(A3) ; port LCD_DATA2
LCD_DATA2_PROT: R216.2 U31.16(B3) ; port LCD_DATA2_PROT
LCD_DATA3: R153.2 R217.1 R235.1 U31.5(A4) ; port LCD_DATA3
LCD_DATA3_PROT: R217.2 U31.15(B4) ; port LCD_DATA3_PROT
LCD_DATA4: R17.1 R218.1 R238.2 U31.6(A5) ; port LCD_DATA4
LCD_DATA4_PROT: R218.2 U31.14(B5) ; port LCD_DATA4_PROT
LCD_DATA5: R156.2 R219.1 R236.1 U31.7(A6) ; port LCD_DATA5
LCD_DATA5_PROT: R219.2 U31.13(B6) ; port LCD_DATA5_PROT
LCD_DATA6: R166.2 R220.1 R237.1 U31.8(A7) ; port LCD_DATA6
LCD_DATA6_PROT: R220.2 U31.12(B7) ; port LCD_DATA6_PROT
LCD_DATA7: R100.1 R221.1 R239.2 U31.9(A8) ; port LCD_DATA7
LCD_DATA7_PROT: R221.2 U31.11(B8) ; port LCD_DATA7_PROT
POR_B: R213.1 ; port POR_B
NetC152_2: C152.2 R213.2 U30.1(A) U30.2(B)
NetU30_4: U30.4(Y) U31.19(#OE)

Not connected (* = marked no-connect by the designer): U31 1(NC)*

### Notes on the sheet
- BOOTSTRAP
- NAND
- BOOT_CFG1[0]
- Row Address Cycles:
- 00 - 3 cycles
- (BOOT_CFG1[0])
- (BOOT_CFG1[1])
- (BOOT_CFG1[3])
- (BOOT_CFG1[4])
- (BOOT_CFG1[2])
- BOOT_CFG1[1]
- 01 - 2 cycles
- 10 - 4 cycles
- 11 - 5 cycles
- (BOOT_CFG1[6])
- (BOOT_CFG1[5])
- (BOOT_CFG1[7])
- BOOT_CFG1[2]
- Number of devices:
- 00 - 1 device
- 01 - 2 devices
- 10 - 4 devices
- BOOT_CFG1[3]
- BOOT_CFG1[4]
- 11 - Reserved
- Pages in Block:
- 00 - 128 pages
- BOOT_CFG1[5]
- 01 - 64 pages
- 10 - 32 pages
- 11 - 256 pages
- BOOT_CFG1[6]
- Samsung's toggle mode DDR NAND
- 0 - Raw NAND
- 1 - Toggle mode NAND
- Boot Device Selection:
- BOOT_CFG1[7]
- 1 - Boot from NAND interface
- BOOT_MODE1
- BOOT_MODE0
- Description
- 0
- 1
- Boot from Fuses
- Serial Downloader
- (near R28) Boot from board settings
- Reserved

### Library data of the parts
C151-C153 = 1000006: as C99-C101 on sheet 10 - CAN, I2C, XBee
J10 = 1001128: CONN HEADER 2POS .100" SGL GOLD; Part_Type: Connector; Manufacturer: Samtec; Manufacturer_Part_Number: TSW-102-07-G-S; Digi_PN: 00120002; Component_Life_Cycle_State: Reviewed; Area: 12.9032; Project: CCWMX6_SBC board
R17 R24 R25 R28 R29 R100 R112 R113 R147 R153 R156 R166 R222 R233-R239 = 1000537: as R40 on sheet 10 - CAN, I2C, XBee
R213 = 1001150: RES 316K OHM 1/10W 1% 0603 SMD; Part_Type: Resistor; Manufacturer: Yageo; Manufacturer_Part_Number: RC0603FR-07316KL; Digi_PN: 13050512; Component_Life_Cycle_State: Reviewed; Area: 1.5; Project: CCWMX6_SBC board; Power_WV_SRF: 100
R214-R221 = 1000076: as R77 on sheet 10 - CAN, I2C, XBee
U30 = 1001160: IC GATE NAND 2-INP HS LOG SC70-5; Manufacturer: Fairchild Semiconductor; Digi_PN: 16050675; Component_Life_Cycle_State: Reviewed; Area: 6.93; Project: CCWMX6_SBC board
U31 = 1001368: IC SWITCH BUS 8BIT FET 20-TSSOP; Manufacturer: Texas Instruments; Digi_PN: 16052042; Component_Life_Cycle_State: Reviewed; Area: 48,18; Project: ConnectCore i.MX6x SOM

## Sheet 13 - GPIO Table, System Power rails.SchDoc: GPIO Table, System Power Rails
size A3; PageSetup: Record=PageOptions¦CenterHorizontal=True¦CenterVertical=True¦PrintScale=1.01¦XCorrection=1.00¦YCorrection=1.00¦PrintKind=0¦BorderSize=5000000¦LeftOffset=0¦BottomOffset=0¦Orientation=2¦PaperLength=4200¦PaperWidth=2970¦Scale=100¦PaperSource=15¦PrintQuality=600¦MediaType=1¦DitherType=10¦PrintScaleMode=1¦PaperKind=A3¦PaperIndex=8; Author: Sébastien MEYER; SheetNumber: 13; SheetTotal: 14
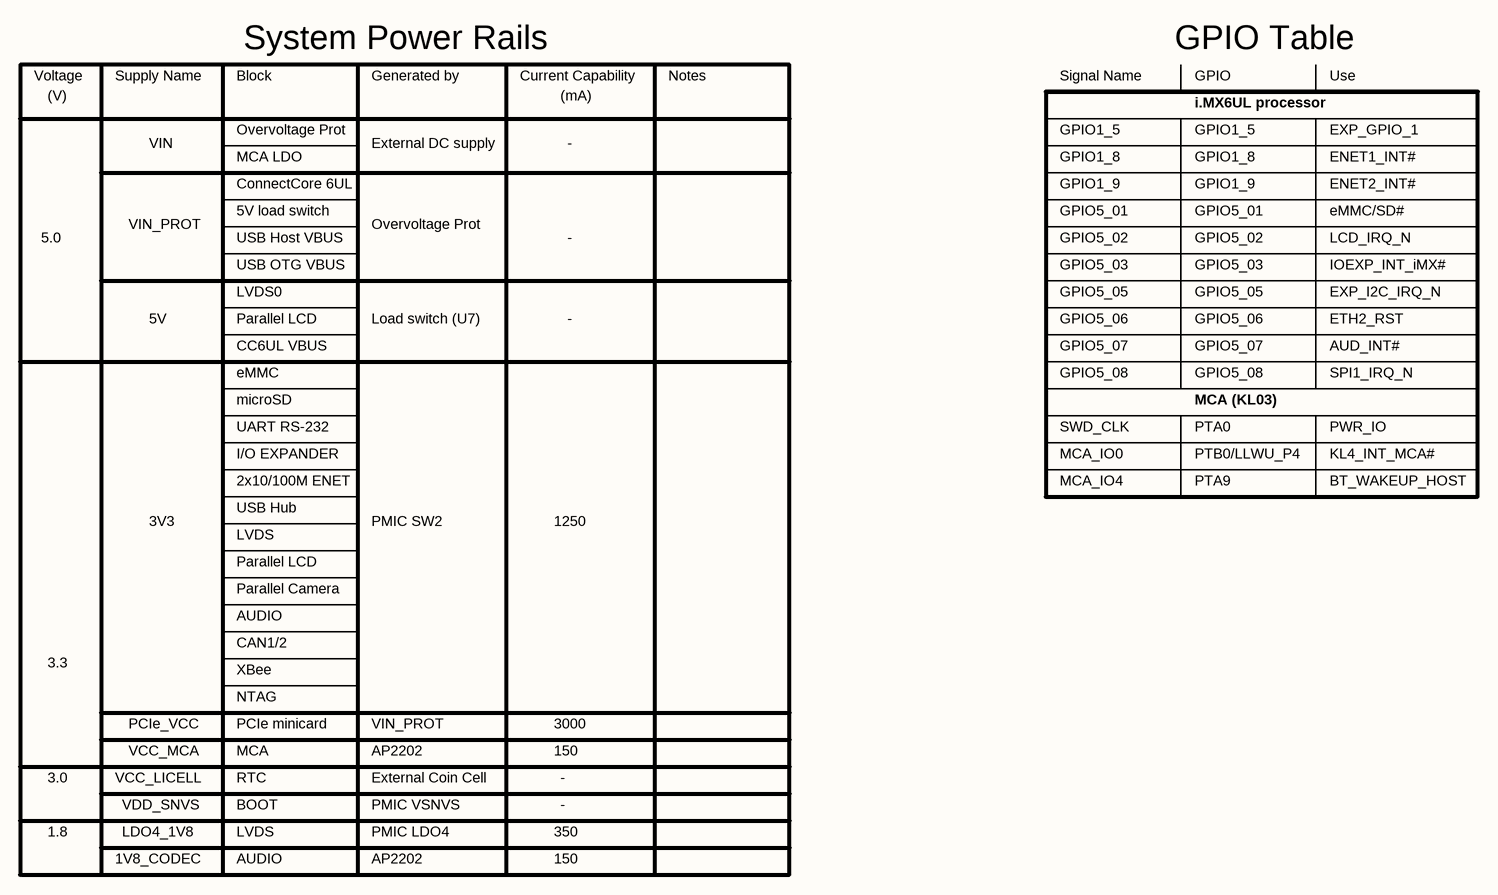
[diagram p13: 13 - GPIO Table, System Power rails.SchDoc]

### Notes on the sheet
- Voltage
- (V)
- Supply Name
- Block
- System Power Rails
- Generated by
- Current Capability
- (mA)
- Notes
- Signal Name
- GPIO Table
- GPIO
- i.MX6UL processor
- Use
- VIN
- Overvoltage Prot
- MCA LDO
- External DC supply
- -
- GPIO1_5
- GPIO1_8
- EXP_GPIO_1
- ENET1_INT#
- 5.0
- VIN_PROT
- USB Host VBUS
- ConnectCore 6UL
- 5V load switch
- GPIO1_9
- GPIO5_01
- GPIO5_02
- ENET2_INT#
- eMMC/SD#
- LCD_IRQ_N
- USB OTG VBUS
- LVDS0
- GPIO5_05
- GPIO5_03
- EXP_I2C_IRQ_N
- IOEXP_INT_iMX#
- 5V
- Parallel LCD
- eMMC
- CC6UL VBUS
- Load switch (U7)
- GPIO5_07
- GPIO5_08
- GPIO5_06
- AUD_INT#
- SPI1_IRQ_N
- ETH2_RST
- microSD
- UART RS-232
- SWD_CLK
- MCA (KL03)
- PTA0
- PWR_IO
- 3V3
- I/O EXPANDER
- 2x10/100M ENET
- USB Hub
- PMIC SW2
- 1250
- MCA_IO0
- MCA_IO4
- PTB0/LLWU_P4
- PTA9
- KL4_INT_MCA#
- BT_WAKEUP_HOST
- LVDS
- AUDIO
- CAN1/2
- Parallel Camera
- 3.3
- XBee
- NTAG
- 3.0
- VCC_LICELL
- VCC_MCA
- PCIe_VCC
- MCA
- RTC
- PCIe minicard
- AP2202
- External Coin Cell
- 150
- 3000
- 1.8
- LDO4_1V8
- VDD_SNVS
- BOOT
- PMIC LDO4
- PMIC VSNVS
- 350
- 1V8_CODEC

## Sheet 14 - History, Mechanicals.SchDoc: History
size A3; PageSetup: Record=PageOptions¦CenterHorizontal=True¦CenterVertical=True¦PrintScale=1.01¦XCorrection=1.00¦YCorrection=1.00¦PrintKind=0¦BorderSize=5000000¦LeftOffset=0¦BottomOffset=0¦Orientation=2¦PaperLength=4200¦PaperWidth=2970¦Scale=100¦PaperSource=15¦PrintQuality=600¦MediaType=1¦DitherType=10¦PrintScaleMode=1¦PaperKind=A3¦PaperIndex=8; Author: Sébastien MEYER; SheetNumber: 14; SheetTotal: 14
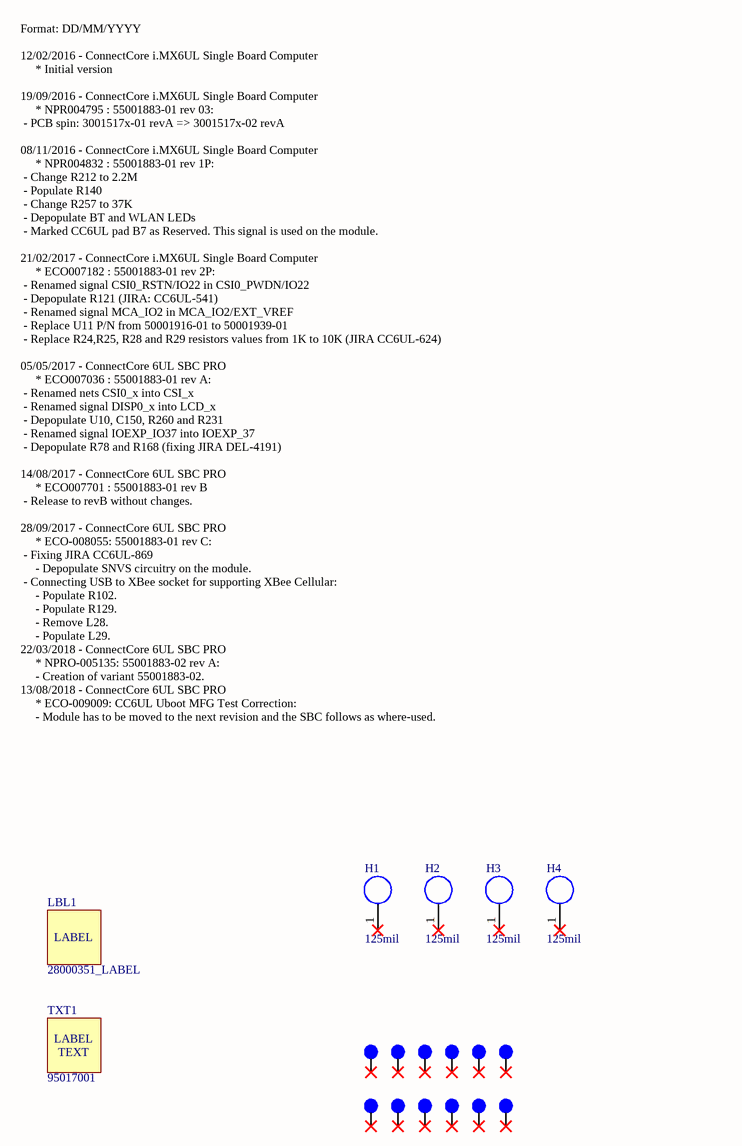
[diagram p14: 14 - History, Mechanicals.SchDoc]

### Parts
FIDUCIAL1  40mil FID  [fiducial_40mil_round]  (value not drawn)
FIDUCIAL2  40mil FID  [fiducial_40mil_round]  (value not drawn)
FIDUCIAL3  40mil FID  [fiducial_40mil_round]  (value not drawn)
FIDUCIAL4  40mil FID  [fiducial_40mil_round]  (value not drawn)  (no BOM)
FIDUCIAL5  40mil FID  [fiducial_40mil_round]  (value not drawn)  (no BOM)
FIDUCIAL6  40mil FID  [fiducial_40mil_round]  (value not drawn)  (no BOM)
FIDUCIAL7  40mil FID  [fiducial_40mil_round]  (value not drawn)
FIDUCIAL8  40mil FID  [fiducial_40mil_round]  (value not drawn)
FIDUCIAL9  40mil FID  [fiducial_40mil_round]  (value not drawn)
FIDUCIAL10  40mil FID  [fiducial_40mil_round]  (value not drawn)  (no BOM)
FIDUCIAL11  40mil FID  [fiducial_40mil_round]  (value not drawn)  (no BOM)
FIDUCIAL12  40mil FID  [fiducial_40mil_round]  (value not drawn)  (no BOM)
H1  125mil  [MH_185_125_NP]
H2  125mil  [MH_185_125_NP]
H3  125mil  [MH_185_125_NP]
H4  125mil  [MH_185_125_NP]
LBL1  28000351_LABEL  [LABEL_10x10]
TXT1  95017001  [0201-2.3]

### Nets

Not connected (* = marked no-connect by the designer): FIDUCIAL1 1(Fid_1)*; FIDUCIAL2 1(Fid_1)*; FIDUCIAL3 1(Fid_1)*; FIDUCIAL4 1(Fid_1)*; FIDUCIAL5 1(Fid_1)*; FIDUCIAL6 1(Fid_1)*; FIDUCIAL7 1(Fid_1)*; FIDUCIAL8 1(Fid_1)*; FIDUCIAL9 1(Fid_1)*; FIDUCIAL10 1(Fid_1)*; FIDUCIAL11 1(Fid_1)*; FIDUCIAL12 1(Fid_1)*; H1 1(TOOL)*; H2 1(TOOL)*; H3 1(TOOL)*; H4 1(TOOL)*

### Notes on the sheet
- Format: DD/MM/YYYY
  12/02/2016 - ConnectCore i.MX6UL Single Board Computer
  * Initial version
  19/09/2016 - ConnectCore i.MX6UL Single Board Computer
  * NPR004795 : 55001883-01 rev 03:
  - PCB spin: 3001517x-01 revA => 3001517x-02 revA
  08/11/2016 - ConnectCore i.MX6UL Single Board Computer
  * NPR004832 : 55001883-01 rev 1P:
  - Change R212 to 2.2M
  - Populate R140
  - Change R257 to 37K
  - Depopulate BT and WLAN LEDs
  - Marked CC6UL pad B7 as Reserved. This signal is used on the module.
  21/02/2017 - ConnectCore i.MX6UL Single Board Computer
  * ECO007182 : 55001883-01 rev 2P:
  - Renamed signal CSI0_RSTN/IO22 in CSI0_PWDN/IO22
  - Depopulate R121 (JIRA: CC6UL-541)
  - Renamed signal MCA_IO2 in MCA_IO2/EXT_VREF
  - Replace U11 P/N from 50001916-01 to 50001939-01
  - Replace R24,R25, R28 and R29 resistors values from 1K to 10K (JIRA CC6UL-624)
  05/05/2017 - ConnectCore 6UL SBC PRO
  * ECO007036 : 55001883-01 rev A:
  - Renamed nets CSI0_x into CSI_x
  - Renamed signal DISP0_x into LCD_x
  - Depopulate U10, C150, R260 and R231
  - Renamed signal IOEXP_IO37 into IOEXP_37
  - Depopulate R78 and R168 (fixing JIRA DEL-4191)
  14/08/2017 - ConnectCore 6UL SBC PRO
  * ECO007701 : 55001883-01 rev B
  - Release to revB without changes.
  28/09/2017 - ConnectCore 6UL SBC PRO
  * ECO-008055: 55001883-01 rev C:
  - Fixing JIRA CC6UL-869
  - Depopulate SNVS circuitry on the module.
  - Connecting USB to XBee socket for supporting XBee Cellular:
  - Populate R102.
  - Populate R129.
  - Remove L28.
  - Populate L29.
  22/03/2018 - ConnectCore 6UL SBC PRO
  * NPRO-005135: 55001883-02 rev A:
  - Creation of variant 55001883-02.
  13/08/2018 - ConnectCore 6UL SBC PRO
  * ECO-009009: CC6UL Uboot MFG Test Correction:
  - Module has to be moved to the next revision and the SBC follows as where-used.

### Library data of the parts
FIDUCIAL1-FIDUCIAL12 = CAD0023: 40 Mil Round Fiducial; Part_Type: Mechanical; Component_Life_Cycle_State: Reviewed; Area: 1; Project: SDR Prototype RF Board
H1-H4 = CAD0006: NPTH for Tooling, 0.125in dia.; Part_Type: Mechanical; Component_Life_Cycle_State: Proven; Area: 0.98; Project: Adjustable Foundation
LBL1 = 1002170: LBL,Poly White Blank 0.40x0.40; Manufacturer: 3M; Manufacturer_Part_Number: TAAE-014000; Noplace: False; Component_Life_Cycle_State: Created; Area: 100; Project: CCWMX6_SBC board
TXT1 = CAD0056: LABEL TEXT; Noplace: False; Note: CAD ONLY; Component_Life_Cycle_State: Created; Area: 0; Project: ConnectCore 6UL SBC PRO

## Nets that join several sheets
3V3: 02 - CCIMX6UL Module (R39.1 R42.1 U36.2 U36.5), 03 - Power, boot strap, reset (J4.1 R22.1), 04 - MicroSD, eMMC, Mini PCIe, microSIM (17 pins), 05 - JTAG, SWD, Console, UART, IO expander (11 pins), 06 - Ethernet (8 pins), 07 - USB OTG, USB HUB, USB Host (6 pins), 08 - Displays and camera (17 pins), 09 - Audio (5 pins), 10 - CAN, I2C, XBee (10 pins), 11 - Expansion Connectors, User LEDs, NTAG (7 pins), 12 - Bootstrap (12 pins)
3V3_INT: 02 - CCIMX6UL Module (9 pins), 05 - JTAG, SWD, Console, UART, IO expander (CAD1.1 R36.2 R149.1)
5V: 02 - CCIMX6UL Module (U11.Y15 U11.Y16), 03 - Power, boot strap, reset (J5.1 R12.2 R21.2), 08 - Displays and camera (R250.1 R251.1 U35.S)
GND: 02 - CCIMX6UL Module (53 pins), 03 - Power, boot strap, reset (36 pins), 04 - MicroSD, eMMC, Mini PCIe, microSIM (69 pins), 05 - JTAG, SWD, Console, UART, IO expander (28 pins), 06 - Ethernet (42 pins), 07 - USB OTG, USB HUB, USB Host (40 pins), 08 - Displays and camera (38 pins), 09 - Audio (33 pins), 10 - CAN, I2C, XBee (16 pins), 11 - Expansion Connectors, User LEDs, NTAG (14 pins), 12 - Bootstrap (16 pins)
LDO4_1V8: 02 - CCIMX6UL Module (U11.D4), 08 - Displays and camera (10 pins)
PCIe_VCC: 04 - MicroSD, eMMC, Mini PCIe, microSIM (21 pins), 10 - CAN, I2C, XBee (L29.1)
SHLD: 04 - MicroSD, eMMC, Mini PCIe, microSIM (J7.11 J7.12), 06 - Ethernet (7 pins), 07 - USB OTG, USB HUB, USB Host (8 pins)
VCC_LICELL: 02 - CCIMX6UL Module (U11.B1), 03 - Power, boot strap, reset (D13.1 R8.2)
VCC_MCA: 02 - CCIMX6UL Module (U11.A8), 03 - Power, boot strap, reset (R83.2 R97.2 R261.2), 05 - JTAG, SWD, Console, UART, IO expander (CAD2.1 J11.1 R150.1), 11 - Expansion Connectors, User LEDs, NTAG (R3.2 R203.2)
VDD_SNVS: 02 - CCIMX6UL Module (U11.W7), 12 - Bootstrap (R24.1 R25.1)
VIN_PROT: 03 - Power, boot strap, reset (14 pins), 04 - MicroSD, eMMC, Mini PCIe, microSIM (7 pins), 05 - JTAG, SWD, Console, UART, IO expander (R151.1 R152.1 R269.1), 07 - USB OTG, USB HUB, USB Host (C62.2 C65.1 U12.7 U14.7), 10 - CAN, I2C, XBee (R101.1), 11 - Expansion Connectors, User LEDs, NTAG (J32.1)
VSYS: 02 - CCIMX6UL Module (R1.1 R2.1), 03 - Power, boot strap, reset (R279.2)
AUD_I2C_SCL: 09 - Audio (U6.51), 10 - CAN, I2C, XBee (R114.2)
AUD_I2C_SDA: 09 - Audio (U6.52), 10 - CAN, I2C, XBee (R115.2)
AUD_INT#: 02 - CCIMX6UL Module (R272.2), 09 - Audio (R93.2 U6.56)
AUD_PWR/IO28: 05 - JTAG, SWD, Console, UART, IO expander (U27.38), 09 - Audio (Q4.G R132.2)
BCKL_PWM: 02 - CCIMX6UL Module (U11.M2), 08 - Displays and camera (J21.37 R258.1)
BOOT_MODE0: 02 - CCIMX6UL Module (U11.V3), 12 - Bootstrap (R24.2 R28.1)
BOOT_MODE1: 02 - CCIMX6UL Module (U11.Y1), 12 - Bootstrap (J10.1 R25.2 R29.1)
CAN1_H: 10 - CAN, I2C, XBee (R104.2 U18.7), 11 - Expansion Connectors, User LEDs, NTAG (J27.2)
CAN1_L: 10 - CAN, I2C, XBee (R104.1 U18.6), 11 - Expansion Connectors, User LEDs, NTAG (J27.1)
CAN2_H: 10 - CAN, I2C, XBee (R116.2 U19.7), 11 - Expansion Connectors, User LEDs, NTAG (J27.5)
CAN2_L: 10 - CAN, I2C, XBee (R116.1 U19.6), 11 - Expansion Connectors, User LEDs, NTAG (J27.4)
CAN_EN1/IO17: 05 - JTAG, SWD, Console, UART, IO expander (U27.27), 10 - CAN, I2C, XBee (R40.2 R263.2)
CAN_EN2/IO15: 05 - JTAG, SWD, Console, UART, IO expander (R282.1), 10 - CAN, I2C, XBee (R264.2 R281.2)
CAN_STBY/IO34: 05 - JTAG, SWD, Console, UART, IO expander (U27.44), 10 - CAN, I2C, XBee (R267.1 U18.8 U19.8)
CSI_DATA02: 02 - CCIMX6UL Module (U11.AA2), 04 - MicroSD, eMMC, Mini PCIe, microSIM (J7.7 R34.1 U2.A3), 08 - Displays and camera (J17.2)
CSI_DATA03: 02 - CCIMX6UL Module (U11.U1), 04 - MicroSD, eMMC, Mini PCIe, microSIM (J7.8 R33.1 U2.A4), 08 - Displays and camera (J17.3)
CSI_DATA04: 02 - CCIMX6UL Module (U11.AA4), 04 - MicroSD, eMMC, Mini PCIe, microSIM (J7.1 R32.1 U2.A5), 08 - Displays and camera (J17.4)
CSI_DATA05: 02 - CCIMX6UL Module (U11.AA5), 04 - MicroSD, eMMC, Mini PCIe, microSIM (J7.2 R31.1 U2.B2), 08 - Displays and camera (J17.5)
CSI_DATA06: 02 - CCIMX6UL Module (U11.W2), 04 - MicroSD, eMMC, Mini PCIe, microSIM (U2.B3), 08 - Displays and camera (J17.6)
CSI_DATA07: 02 - CCIMX6UL Module (U11.Y2), 04 - MicroSD, eMMC, Mini PCIe, microSIM (U2.B4), 08 - Displays and camera (J17.7)
CSI_DATA08: 02 - CCIMX6UL Module (U11.W3), 04 - MicroSD, eMMC, Mini PCIe, microSIM (U2.B5), 08 - Displays and camera (J17.8)
CSI_DATA09: 02 - CCIMX6UL Module (U11.W5), 04 - MicroSD, eMMC, Mini PCIe, microSIM (U2.B6), 08 - Displays and camera (J17.9)
CSI_GPIO/IO31: 05 - JTAG, SWD, Console, UART, IO expander (U27.41), 08 - Displays and camera (J17.15)
CSI_HSYNC: 02 - CCIMX6UL Module (U11.V1), 04 - MicroSD, eMMC, Mini PCIe, microSIM (R243.1 R244.1 U33.4), 08 - Displays and camera (J17.13)
CSI_I2C_SCL: 08 - Displays and camera (J17.18), 10 - CAN, I2C, XBee (R108.2)
CSI_I2C_SDA: 08 - Displays and camera (J17.19), 10 - CAN, I2C, XBee (R111.2)
CSI_MCLK: 02 - CCIMX6UL Module (U11.R1), 08 - Displays and camera (J17.11)
CSI_PIXCLK: 02 - CCIMX6UL Module (U11.T1), 08 - Displays and camera (J17.12)
CSI_PWDN/IO22: 05 - JTAG, SWD, Console, UART, IO expander (R121.1 U27.32), 08 - Displays and camera (J17.16)
CSI_VSYNC: 02 - CCIMX6UL Module (U11.AA3), 04 - MicroSD, eMMC, Mini PCIe, microSIM (R245.1 R246.1 U34.4), 08 - Displays and camera (J17.14)
DISP_5V_PWR/IO29: 05 - JTAG, SWD, Console, UART, IO expander (U27.39), 08 - Displays and camera (Q11.G R252.2)
eMMC/SD#: 02 - CCIMX6UL Module (R38.1 U11.V14), 04 - MicroSD, eMMC, Mini PCIe, microSIM (U33.6 U34.6)
eMMC_PWR/IO8: 04 - MicroSD, eMMC, Mini PCIe, microSIM (Q6.G R186.2), 05 - JTAG, SWD, Console, UART, IO expander (U27.15)
ENET1_INT#: 02 - CCIMX6UL Module (U11.Y19), 06 - Ethernet (R53.1 U16.14)
ENET1_RX_DATA0: 02 - CCIMX6UL Module (U11.L21), 06 - Ethernet (R58.2 R62.1 U16.8)
ENET1_RX_DATA1: 02 - CCIMX6UL Module (U11.E21), 06 - Ethernet (R59.2 R63.1 U16.7)
ENET1_RX_EN: 02 - CCIMX6UL Module (U11.K21), 06 - Ethernet (R57.2 R61.1 U16.11)
ENET1_RX_ER: 02 - CCIMX6UL Module (U11.J21), 06 - Ethernet (R56.2 R60.1 U16.10)
ENET1_TX_CLK: 02 - CCIMX6UL Module (U11.F21), 06 - Ethernet (U16.5)
ENET1_TX_DATA0: 02 - CCIMX6UL Module (U11.D21), 06 - Ethernet (U16.17)
ENET1_TX_DATA1: 02 - CCIMX6UL Module (U11.H21), 06 - Ethernet (U16.18)
ENET1_TX_EN: 02 - CCIMX6UL Module (U11.G21), 06 - Ethernet (U16.16)
ENET2_INT#: 02 - CCIMX6UL Module (U11.U19), 06 - Ethernet (R154.1 U24.14)
ENET2_RX_DATA0: 02 - CCIMX6UL Module (U11.W17), 06 - Ethernet (R10.1 R160.2 R164.1), 07 - USB OTG, USB HUB, USB Host (R18.1)
ENET2_RX_DATA1: 02 - CCIMX6UL Module (U11.W19), 06 - Ethernet (R9.1 R161.2 R165.1), 07 - USB OTG, USB HUB, USB Host (R19.2)
ENET2_RX_EN: 02 - CCIMX6UL Module (U11.V20), 06 - Ethernet (R159.2 R163.1 U24.11)
ENET2_RX_ER: 02 - CCIMX6UL Module (U11.V19), 06 - Ethernet (R158.2 R162.1 U24.10)
ENET2_TX_CLK: 02 - CCIMX6UL Module (U11.V18), 06 - Ethernet (U24.5)
ENET2_TX_DATA0: 02 - CCIMX6UL Module (U11.W18), 06 - Ethernet (U24.17)
ENET2_TX_DATA1: 02 - CCIMX6UL Module (U11.W20), 06 - Ethernet (U24.18)
ENET2_TX_EN: 02 - CCIMX6UL Module (U11.V17), 06 - Ethernet (U24.16)
ENET_MDC: 02 - CCIMX6UL Module (U11.AA19), 06 - Ethernet (R50.2 U16.13 U24.13)
ENET_MDIO: 02 - CCIMX6UL Module (U11.AA20), 06 - Ethernet (R49.2 U16.12 U24.12)
ENET_PWR/IO26: 05 - JTAG, SWD, Console, UART, IO expander (U27.36), 06 - Ethernet (Q7.G R51.2)
ETH2_RST: 02 - CCIMX6UL Module (U11.W15), 06 - Ethernet (C19.2 R90.2 U24.15)
EXP_GPIO_1: 02 - CCIMX6UL Module (U11.W1), 11 - Expansion Connectors, User LEDs, NTAG (J30.11)
EXP_GPIO_2: 02 - CCIMX6UL Module (U11.Y14), 11 - Expansion Connectors, User LEDs, NTAG (J30.12)
EXP_GPIO_3: 02 - CCIMX6UL Module (U11.Y13), 11 - Expansion Connectors, User LEDs, NTAG (R253.2)
EXP_I2C_GPIO/IO32: 05 - JTAG, SWD, Console, UART, IO expander (U27.42), 11 - Expansion Connectors, User LEDs, NTAG (J28.5)
EXP_I2C_IRQ_N: 02 - CCIMX6UL Module (R271.2), 11 - Expansion Connectors, User LEDs, NTAG (J28.4 R117.2)
EXP_I2C_SCL: 10 - CAN, I2C, XBee (R106.2), 11 - Expansion Connectors, User LEDs, NTAG (J28.1)
EXP_I2C_SDA: 10 - CAN, I2C, XBee (R107.2), 11 - Expansion Connectors, User LEDs, NTAG (J28.2)
I2C1_SCL: 02 - CCIMX6UL Module (R274.2 U36.6), 10 - CAN, I2C, XBee (8 pins)
I2C1_SDA: 02 - CCIMX6UL Module (R275.2 U36.3), 10 - CAN, I2C, XBee (8 pins)
IOEXP_3: 05 - JTAG, SWD, Console, UART, IO expander (U27.6), 11 - Expansion Connectors, User LEDs, NTAG (J30.1)
IOEXP_4: 05 - JTAG, SWD, Console, UART, IO expander (U27.7), 11 - Expansion Connectors, User LEDs, NTAG (J30.3)
IOEXP_5: 05 - JTAG, SWD, Console, UART, IO expander (U27.8), 11 - Expansion Connectors, User LEDs, NTAG (J30.4)
IOEXP_6: 05 - JTAG, SWD, Console, UART, IO expander (U27.13), 11 - Expansion Connectors, User LEDs, NTAG (J30.2)
IOEXP_37: 05 - JTAG, SWD, Console, UART, IO expander (U27.47), 11 - Expansion Connectors, User LEDs, NTAG (R89.1)
IOEXP_I2C0_SCL: 05 - JTAG, SWD, Console, UART, IO expander (U27.29), 10 - CAN, I2C, XBee (R187.2)
IOEXP_I2C0_SDA: 05 - JTAG, SWD, Console, UART, IO expander (U27.30), 10 - CAN, I2C, XBee (R188.2)
IOEXP_INT_iMX#: 02 - CCIMX6UL Module (R283.2), 05 - JTAG, SWD, Console, UART, IO expander (R254.2 U27.46)
IOEXP_INT_MCA#: 02 - CCIMX6UL Module (U11.A2), 05 - JTAG, SWD, Console, UART, IO expander (R262.1 U27.25)
IOEXP_SWD_CLK/LVDS_FLIP: 05 - JTAG, SWD, Console, UART, IO expander (CAD3.4 J37.4 U27.17), 08 - Displays and camera (R249.1)
IOEXP_SWD_DIO/LVDS_RF: 05 - JTAG, SWD, Console, UART, IO expander (CAD3.2 J37.2 U27.20), 08 - Displays and camera (R248.1)
JTAG_MOD: 02 - CCIMX6UL Module (U11.AA15), 05 - JTAG, SWD, Console, UART, IO expander (R37.2)
JTAG_TCK/SAI2_RX_DATA: 02 - CCIMX6UL Module (U11.W21), 05 - JTAG, SWD, Console, UART, IO expander (CAD1.4), 09 - Audio (R191.1)
JTAG_TDI/SAI2_TX_BCLK: 02 - CCIMX6UL Module (U11.V21), 05 - JTAG, SWD, Console, UART, IO expander (CAD1.8), 09 - Audio (R131.1)
JTAG_TDO/SAI2_TX_SYNC: 02 - CCIMX6UL Module (U11.Y21), 05 - JTAG, SWD, Console, UART, IO expander (CAD1.6), 09 - Audio (R189.1)
JTAG_TMS/SAI2_MCLK: 02 - CCIMX6UL Module (U11.AA16), 05 - JTAG, SWD, Console, UART, IO expander (CAD1.2), 09 - Audio (R94.1)
JTAG_TRST_N/SAI2_TX_DATA: 02 - CCIMX6UL Module (U11.U21), 05 - JTAG, SWD, Console, UART, IO expander (CAD1.9 R36.1), 09 - Audio (R190.1)
LCD_CLK: 02 - CCIMX6UL Module (U11.C21), 08 - Displays and camera (J21.27 U25.F9)
LCD_DATA0: 02 - CCIMX6UL Module (U11.A18), 12 - Bootstrap (R112.2 R214.1 R222.1 U31.2)
LCD_DATA0_PROT: 08 - Displays and camera (J21.2 U25.H5), 12 - Bootstrap (R214.2 U31.18)
LCD_DATA1: 02 - CCIMX6UL Module (U11.A10), 12 - Bootstrap (R113.2 R215.1 R233.1 U31.3)
LCD_DATA1_PROT: 08 - Displays and camera (J21.3 U25.J5), 12 - Bootstrap (R215.2 U31.17)
LCD_DATA2: 02 - CCIMX6UL Module (U11.A12), 12 - Bootstrap (R147.2 R216.1 R234.1 U31.4)
LCD_DATA2_PROT: 08 - Displays and camera (J21.4 U25.H6), 12 - Bootstrap (R216.2 U31.16)
LCD_DATA3: 02 - CCIMX6UL Module (U11.A17), 12 - Bootstrap (R153.2 R217.1 R235.1 U31.5)
LCD_DATA3_PROT: 08 - Displays and camera (J21.5 U25.J6), 12 - Bootstrap (R217.2 U31.15)
LCD_DATA4: 02 - CCIMX6UL Module (U11.A20), 12 - Bootstrap (R17.1 R218.1 R238.2 U31.6)
LCD_DATA4_PROT: 08 - Displays and camera (J21.6 U25.H7), 12 - Bootstrap (R218.2 U31.14)
LCD_DATA5: 02 - CCIMX6UL Module (U11.A14), 12 - Bootstrap (R156.2 R219.1 R236.1 U31.7)
LCD_DATA5_PROT: 08 - Displays and camera (J21.7 U25.J7), 12 - Bootstrap (R219.2 U31.13)
LCD_DATA6: 02 - CCIMX6UL Module (U11.A16), 12 - Bootstrap (R166.2 R220.1 R237.1 U31.8)
LCD_DATA6_PROT: 08 - Displays and camera (J21.8 U25.H1), 12 - Bootstrap (R220.2 U31.12)
LCD_DATA7: 02 - CCIMX6UL Module (U11.A15), 12 - Bootstrap (R100.1 R221.1 R239.2 U31.9)
LCD_DATA7_PROT: 08 - Displays and camera (J21.9 U25.J1), 12 - Bootstrap (R221.2 U31.11)
LCD_DATA8: 02 - CCIMX6UL Module (U11.L1), 08 - Displays and camera (J21.10 U25.H2)
LCD_DATA9: 02 - CCIMX6UL Module (U11.M1), 08 - Displays and camera (J21.11 U25.J2)
LCD_DATA10: 02 - CCIMX6UL Module (U11.V7), 08 - Displays and camera (J21.12 U25.H3)
LCD_DATA11: 02 - CCIMX6UL Module (U11.V13), 08 - Displays and camera (J21.13 U25.J3)
LCD_DATA12: 02 - CCIMX6UL Module (U11.V8), 08 - Displays and camera (J21.14 U25.D2)
LCD_DATA13: 02 - CCIMX6UL Module (U11.U20), 08 - Displays and camera (J21.15 U25.D1)
LCD_DATA14: 02 - CCIMX6UL Module (U11.Y12), 08 - Displays and camera (J21.16 U25.E2)
LCD_DATA15: 02 - CCIMX6UL Module (U11.V9), 08 - Displays and camera (J21.17 U25.E1)
LCD_DATA16: 02 - CCIMX6UL Module (U11.W10), 08 - Displays and camera (J21.18 U25.F2)
LCD_DATA17: 02 - CCIMX6UL Module (U11.Y20), 08 - Displays and camera (J21.19 U25.F1)
LCD_DATA18: 02 - CCIMX6UL Module (U11.V10), 08 - Displays and camera (R41.1)
LCD_DATA19: 02 - CCIMX6UL Module (U11.Y17), 08 - Displays and camera (R207.1), 11 - Expansion Connectors, User LEDs, NTAG (R256.2)
LCD_DATA20/SPI1_CLK: 02 - CCIMX6UL Module (U11.V12), 08 - Displays and camera (R208.1), 11 - Expansion Connectors, User LEDs, NTAG (J34.2)
LCD_DATA21/SPI1_SS0: 02 - CCIMX6UL Module (U11.Y9), 08 - Displays and camera (R209.1), 11 - Expansion Connectors, User LEDs, NTAG (J34.5)
LCD_DATA22/SPI1_MOSI: 02 - CCIMX6UL Module (U11.N19), 08 - Displays and camera (R210.1), 11 - Expansion Connectors, User LEDs, NTAG (J34.4)
LCD_DATA23/SPI1_MISO: 02 - CCIMX6UL Module (U11.N20), 08 - Displays and camera (R211.1), 11 - Expansion Connectors, User LEDs, NTAG (J34.3)
LCD_DRDY: 02 - CCIMX6UL Module (U11.A9), 08 - Displays and camera (J21.31 U25.G9)
LCD_HSYNC: 02 - CCIMX6UL Module (U11.B21), 08 - Displays and camera (J21.29 U25.J9)
LCD_I2C_SCL: 08 - Displays and camera (J21.33 J31.17), 10 - CAN, I2C, XBee (R103.2)
LCD_I2C_SDA: 08 - Displays and camera (J21.34 J31.18), 10 - CAN, I2C, XBee (R105.2)
LCD_IRQ_N: 02 - CCIMX6UL Module (R270.2), 08 - Displays and camera (J21.35 J31.19 R78.2 R168.2)
LCD_RESET: 02 - CCIMX6UL Module (U11.A19), 08 - Displays and camera (J21.32 R259.1)
LCD_VSYNC: 02 - CCIMX6UL Module (U11.A11), 08 - Displays and camera (J21.30 U25.H9)
LDOG: 02 - CCIMX6UL Module (U11.E1), 03 - Power, boot strap, reset (C55.1 U1.3)
LINE_IN_A_L: 09 - Audio (L21.1), 11 - Expansion Connectors, User LEDs, NTAG (J26.4)
LINE_IN_A_R: 09 - Audio (L20.1), 11 - Expansion Connectors, User LEDs, NTAG (J26.3)
LINE_OUT_L: 09 - Audio (U6.23), 11 - Expansion Connectors, User LEDs, NTAG (J26.7)
LINE_OUT_R: 09 - Audio (U6.24), 11 - Expansion Connectors, User LEDs, NTAG (J26.6)
LVDS_PD#/IO30: 05 - JTAG, SWD, Console, UART, IO expander (U27.40), 08 - Displays and camera (R266.2 U25.D8)
MCA_CLKOUT32K: 02 - CCIMX6UL Module (U11.C4), 05 - JTAG, SWD, Console, UART, IO expander (R81.1)
MCA_IO1: 02 - CCIMX6UL Module (U11.B2), 11 - Expansion Connectors, User LEDs, NTAG (J30.7 R201.1)
MCA_IO2/EXT_VREF: 02 - CCIMX6UL Module (U11.B5), 11 - Expansion Connectors, User LEDs, NTAG (R181.1)
MCA_IO3: 02 - CCIMX6UL Module (U11.C3), 11 - Expansion Connectors, User LEDs, NTAG (J30.8)
MCA_IO5: 02 - CCIMX6UL Module (U11.B6), 11 - Expansion Connectors, User LEDs, NTAG (J34.6)
MCA_RESET_N: 02 - CCIMX6UL Module (U11.A5), 03 - Power, boot strap, reset (R97.1 R98.2), 05 - JTAG, SWD, Console, UART, IO expander (CAD2.10 J11.10)
MCA_SWD_CLK/PWR_IO: 02 - CCIMX6UL Module (U11.A6), 03 - Power, boot strap, reset (R83.1 R99.2), 05 - JTAG, SWD, Console, UART, IO expander (CAD2.4 J11.4)
MCA_SWD_DIO/ETH1_RST: 02 - CCIMX6UL Module (U11.A7), 05 - JTAG, SWD, Console, UART, IO expander (CAD2.2 J11.2), 06 - Ethernet (C18.2 R26.2 U16.15)
MIC_N: 09 - Audio (L24.1), 11 - Expansion Connectors, User LEDs, NTAG (J26.1)
MIC_P: 09 - Audio (L19.1), 11 - Expansion Connectors, User LEDs, NTAG (J26.2)
NTAG/IOEXP_I2C1_SCL: 05 - JTAG, SWD, Console, UART, IO expander (R265.1 U27.34), 11 - Expansion Connectors, User LEDs, NTAG (R229.1)
NTAG/IOEXP_I2C1_SDA: 05 - JTAG, SWD, Console, UART, IO expander (R247.1 U27.35), 11 - Expansion Connectors, User LEDs, NTAG (R230.1)
NTAG_FD/IO35: 05 - JTAG, SWD, Console, UART, IO expander (U27.45), 11 - Expansion Connectors, User LEDs, NTAG (R205.1)
NTAG_I2C_SCL: 10 - CAN, I2C, XBee (R199.2), 11 - Expansion Connectors, User LEDs, NTAG (R227.1)
NTAG_I2C_SDA: 10 - CAN, I2C, XBee (R200.2), 11 - Expansion Connectors, User LEDs, NTAG (R228.1)
ON/OFF: 02 - CCIMX6UL Module (U11.W14), 03 - Power, boot strap, reset (R167.2)
PCIE_DIS_N/IO12: 04 - MicroSD, eMMC, Mini PCIe, microSIM (J12.20), 05 - JTAG, SWD, Console, UART, IO expander (U27.19)
PCIE_I2C_SCL: 04 - MicroSD, eMMC, Mini PCIe, microSIM (J12.30), 10 - CAN, I2C, XBee (R95.2)
PCIE_I2C_SDA: 04 - MicroSD, eMMC, Mini PCIe, microSIM (J12.32), 10 - CAN, I2C, XBee (R96.2)
PCIE_VCC_EN/IO27: 04 - MicroSD, eMMC, Mini PCIe, microSIM (R141.1), 05 - JTAG, SWD, Console, UART, IO expander (U27.37)
PCIE_WAKE_N/IO38: 04 - MicroSD, eMMC, Mini PCIe, microSIM (J12.1 R241.1), 05 - JTAG, SWD, Console, UART, IO expander (U27.48)
PCM_CLK: 02 - CCIMX6UL Module (J13.5 U11.C20), 09 - Audio (R192.1)
PCM_IN: 02 - CCIMX6UL Module (J13.6 U11.D20), 09 - Audio (R195.1)
PCM_OUT: 02 - CCIMX6UL Module (J13.7 U11.C17), 09 - Audio (R194.1)
PCM_SYNC: 02 - CCIMX6UL Module (J13.8 U11.C18), 09 - Audio (R193.1)
POR_B: 02 - CCIMX6UL Module (U11.P1), 05 - JTAG, SWD, Console, UART, IO expander (CAD1.10 R257.1), 12 - Bootstrap (R213.1)
PWR_EN/IO14: 03 - Power, boot strap, reset (R22.2 U7.4), 05 - JTAG, SWD, Console, UART, IO expander (U27.21)
PWR_ON: 02 - CCIMX6UL Module (U11.W8), 03 - Power, boot strap, reset (Q9.G R212.2)
RF_KILL_SW#/IO2: 02 - CCIMX6UL Module (R260.2 U10.6), 05 - JTAG, SWD, Console, UART, IO expander (R232.2 U27.5)
RS232_3_CTS_N: 05 - JTAG, SWD, Console, UART, IO expander (U9.5), 11 - Expansion Connectors, User LEDs, NTAG (J29.9)
RS232_3_RTS_N: 05 - JTAG, SWD, Console, UART, IO expander (U9.10), 11 - Expansion Connectors, User LEDs, NTAG (J29.8)
RS232_3_RX: 05 - JTAG, SWD, Console, UART, IO expander (U9.4), 11 - Expansion Connectors, User LEDs, NTAG (J29.7)
RS232_3_TX: 05 - JTAG, SWD, Console, UART, IO expander (U9.9), 11 - Expansion Connectors, User LEDs, NTAG (J29.6)
RS232_IOEXP_2_RX: 05 - JTAG, SWD, Console, UART, IO expander (U9.6), 11 - Expansion Connectors, User LEDs, NTAG (J29.2)
RS232_IOEXP_2_TX: 05 - JTAG, SWD, Console, UART, IO expander (U9.11), 11 - Expansion Connectors, User LEDs, NTAG (J29.1)
SPI1_IRQ_N: 02 - CCIMX6UL Module (R273.2), 11 - Expansion Connectors, User LEDs, NTAG (J34.7 R122.2)
UART2_CTS_N/CAN2_TX: 02 - CCIMX6UL Module (U11.N21), 10 - CAN, I2C, XBee (J24.5 R145.2 TP12.1 U19.1), 11 - Expansion Connectors, User LEDs, NTAG (J29.14)
UART2_RTS_N/CAN2_RX: 02 - CCIMX6UL Module (U11.M21), 10 - CAN, I2C, XBee (J24.9 TP14.1 U19.4), 11 - Expansion Connectors, User LEDs, NTAG (J29.13)
UART2_RX: 02 - CCIMX6UL Module (U11.R21), 10 - CAN, I2C, XBee (J23.2 TP10.1), 11 - Expansion Connectors, User LEDs, NTAG (J29.12)
UART2_TX: 02 - CCIMX6UL Module (U11.T21), 10 - CAN, I2C, XBee (J23.3 TP11.1), 11 - Expansion Connectors, User LEDs, NTAG (J29.11)
UART3_CTS_N/CAN1_TX: 02 - CCIMX6UL Module (U11.P19), 05 - JTAG, SWD, Console, UART, IO expander (R125.1), 10 - CAN, I2C, XBee (R77.1)
UART3_RTS_N/CAN1_RX: 02 - CCIMX6UL Module (U11.P20), 05 - JTAG, SWD, Console, UART, IO expander (R155.1), 10 - CAN, I2C, XBee (R123.1)
UART3_RX: 02 - CCIMX6UL Module (U11.R19), 05 - JTAG, SWD, Console, UART, IO expander (U9.19)
UART3_TX: 02 - CCIMX6UL Module (U11.R20), 05 - JTAG, SWD, Console, UART, IO expander (U9.14)
UART5_RX: 02 - CCIMX6UL Module (U11.AA7), 05 - JTAG, SWD, Console, UART, IO expander (D6.2 J9.2)
UART5_TX: 02 - CCIMX6UL Module (U11.AA6), 05 - JTAG, SWD, Console, UART, IO expander (D7.2 J9.1)
USB_OTG_D_N: 02 - CCIMX6UL Module (U11.AA9), 07 - USB OTG, USB HUB, USB Host (L10.1)
USB_OTG_D_P: 02 - CCIMX6UL Module (U11.AA8), 07 - USB OTG, USB HUB, USB Host (L10.4)
USB_OTG_ID: 02 - CCIMX6UL Module (U11.AA13), 07 - USB OTG, USB HUB, USB Host (J16.4 U20.1)
USB_OTG_OC: 02 - CCIMX6UL Module (U11.AA14), 07 - USB OTG, USB HUB, USB Host (R16.2), 11 - Expansion Connectors, User LEDs, NTAG (R118.1)
USB_OTG_PWR: 02 - CCIMX6UL Module (U11.AA12), 07 - USB OTG, USB HUB, USB Host (R15.1), 11 - Expansion Connectors, User LEDs, NTAG (R80.1)
USB_OTG_VBUS: 02 - CCIMX6UL Module (U11.AA11 U11.Y11), 07 - USB OTG, USB HUB, USB Host (U15.D)
USB_PWR/IO21: 05 - JTAG, SWD, Console, UART, IO expander (U27.31), 07 - USB OTG, USB HUB, USB Host (Q10.G R69.2)
USBH3_D_N: 04 - MicroSD, eMMC, Mini PCIe, microSIM (J12.36), 07 - USB OTG, USB HUB, USB Host (L14.2)
USBH3_D_P: 04 - MicroSD, eMMC, Mini PCIe, microSIM (J12.38), 07 - USB OTG, USB HUB, USB Host (L14.3)
USBH4_D_N: 07 - USB OTG, USB HUB, USB Host (L16.2), 10 - CAN, I2C, XBee (R129.1), 11 - Expansion Connectors, User LEDs, NTAG (J32.3)
USBH4_D_P: 07 - USB OTG, USB HUB, USB Host (L16.3), 10 - CAN, I2C, XBee (R102.1), 11 - Expansion Connectors, User LEDs, NTAG (J32.2)
USBH4_OC_N: 07 - USB OTG, USB HUB, USB Host (U13.21), 11 - Expansion Connectors, User LEDs, NTAG (J32.4)
USBH4_PWR_EN: 07 - USB OTG, USB HUB, USB Host (U13.20), 11 - Expansion Connectors, User LEDs, NTAG (J32.5)
USBH_D_N: 02 - CCIMX6UL Module (U11.AA18), 07 - USB OTG, USB HUB, USB Host (U13.30)
USBH_D_P: 02 - CCIMX6UL Module (U11.AA17), 07 - USB OTG, USB HUB, USB Host (U13.31)
USER_LED1/IO23: 05 - JTAG, SWD, Console, UART, IO expander (U27.33), 11 - Expansion Connectors, User LEDs, NTAG (R119.2)
VIN_PRESENT: 02 - CCIMX6UL Module (U11.A4), 03 - Power, boot strap, reset (R182.2 R183.2 R184.2)
VPWR: 02 - CCIMX6UL Module (U11.D1), 03 - Power, boot strap, reset (R225.2 R226.2)
XBEE_IDENT/IO33: 05 - JTAG, SWD, Console, UART, IO expander (U27.43), 10 - CAN, I2C, XBee (J24.1 J25.1 R136.1)
XBEE_ON/SLP_N/IO11: 05 - JTAG, SWD, Console, UART, IO expander (U27.18), 10 - CAN, I2C, XBee (J24.8 Q5.G)
XBEE_RSTN/IO7: 05 - JTAG, SWD, Console, UART, IO expander (U27.14), 10 - CAN, I2C, XBee (J23.5 TP15.1)
XBEE_SLP_RQ/IO9: 05 - JTAG, SWD, Console, UART, IO expander (U27.16), 10 - CAN, I2C, XBee (J23.9 R146.2 TP13.1)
